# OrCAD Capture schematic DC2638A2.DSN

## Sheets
1 PAGE5: size C; company: ANALOG DEVICES; note: DEMO BOARD BILL OF MATERIALS; note: HIGH EFFICIENCY, POLY-PHASE, DC/DC STEP-DOWN
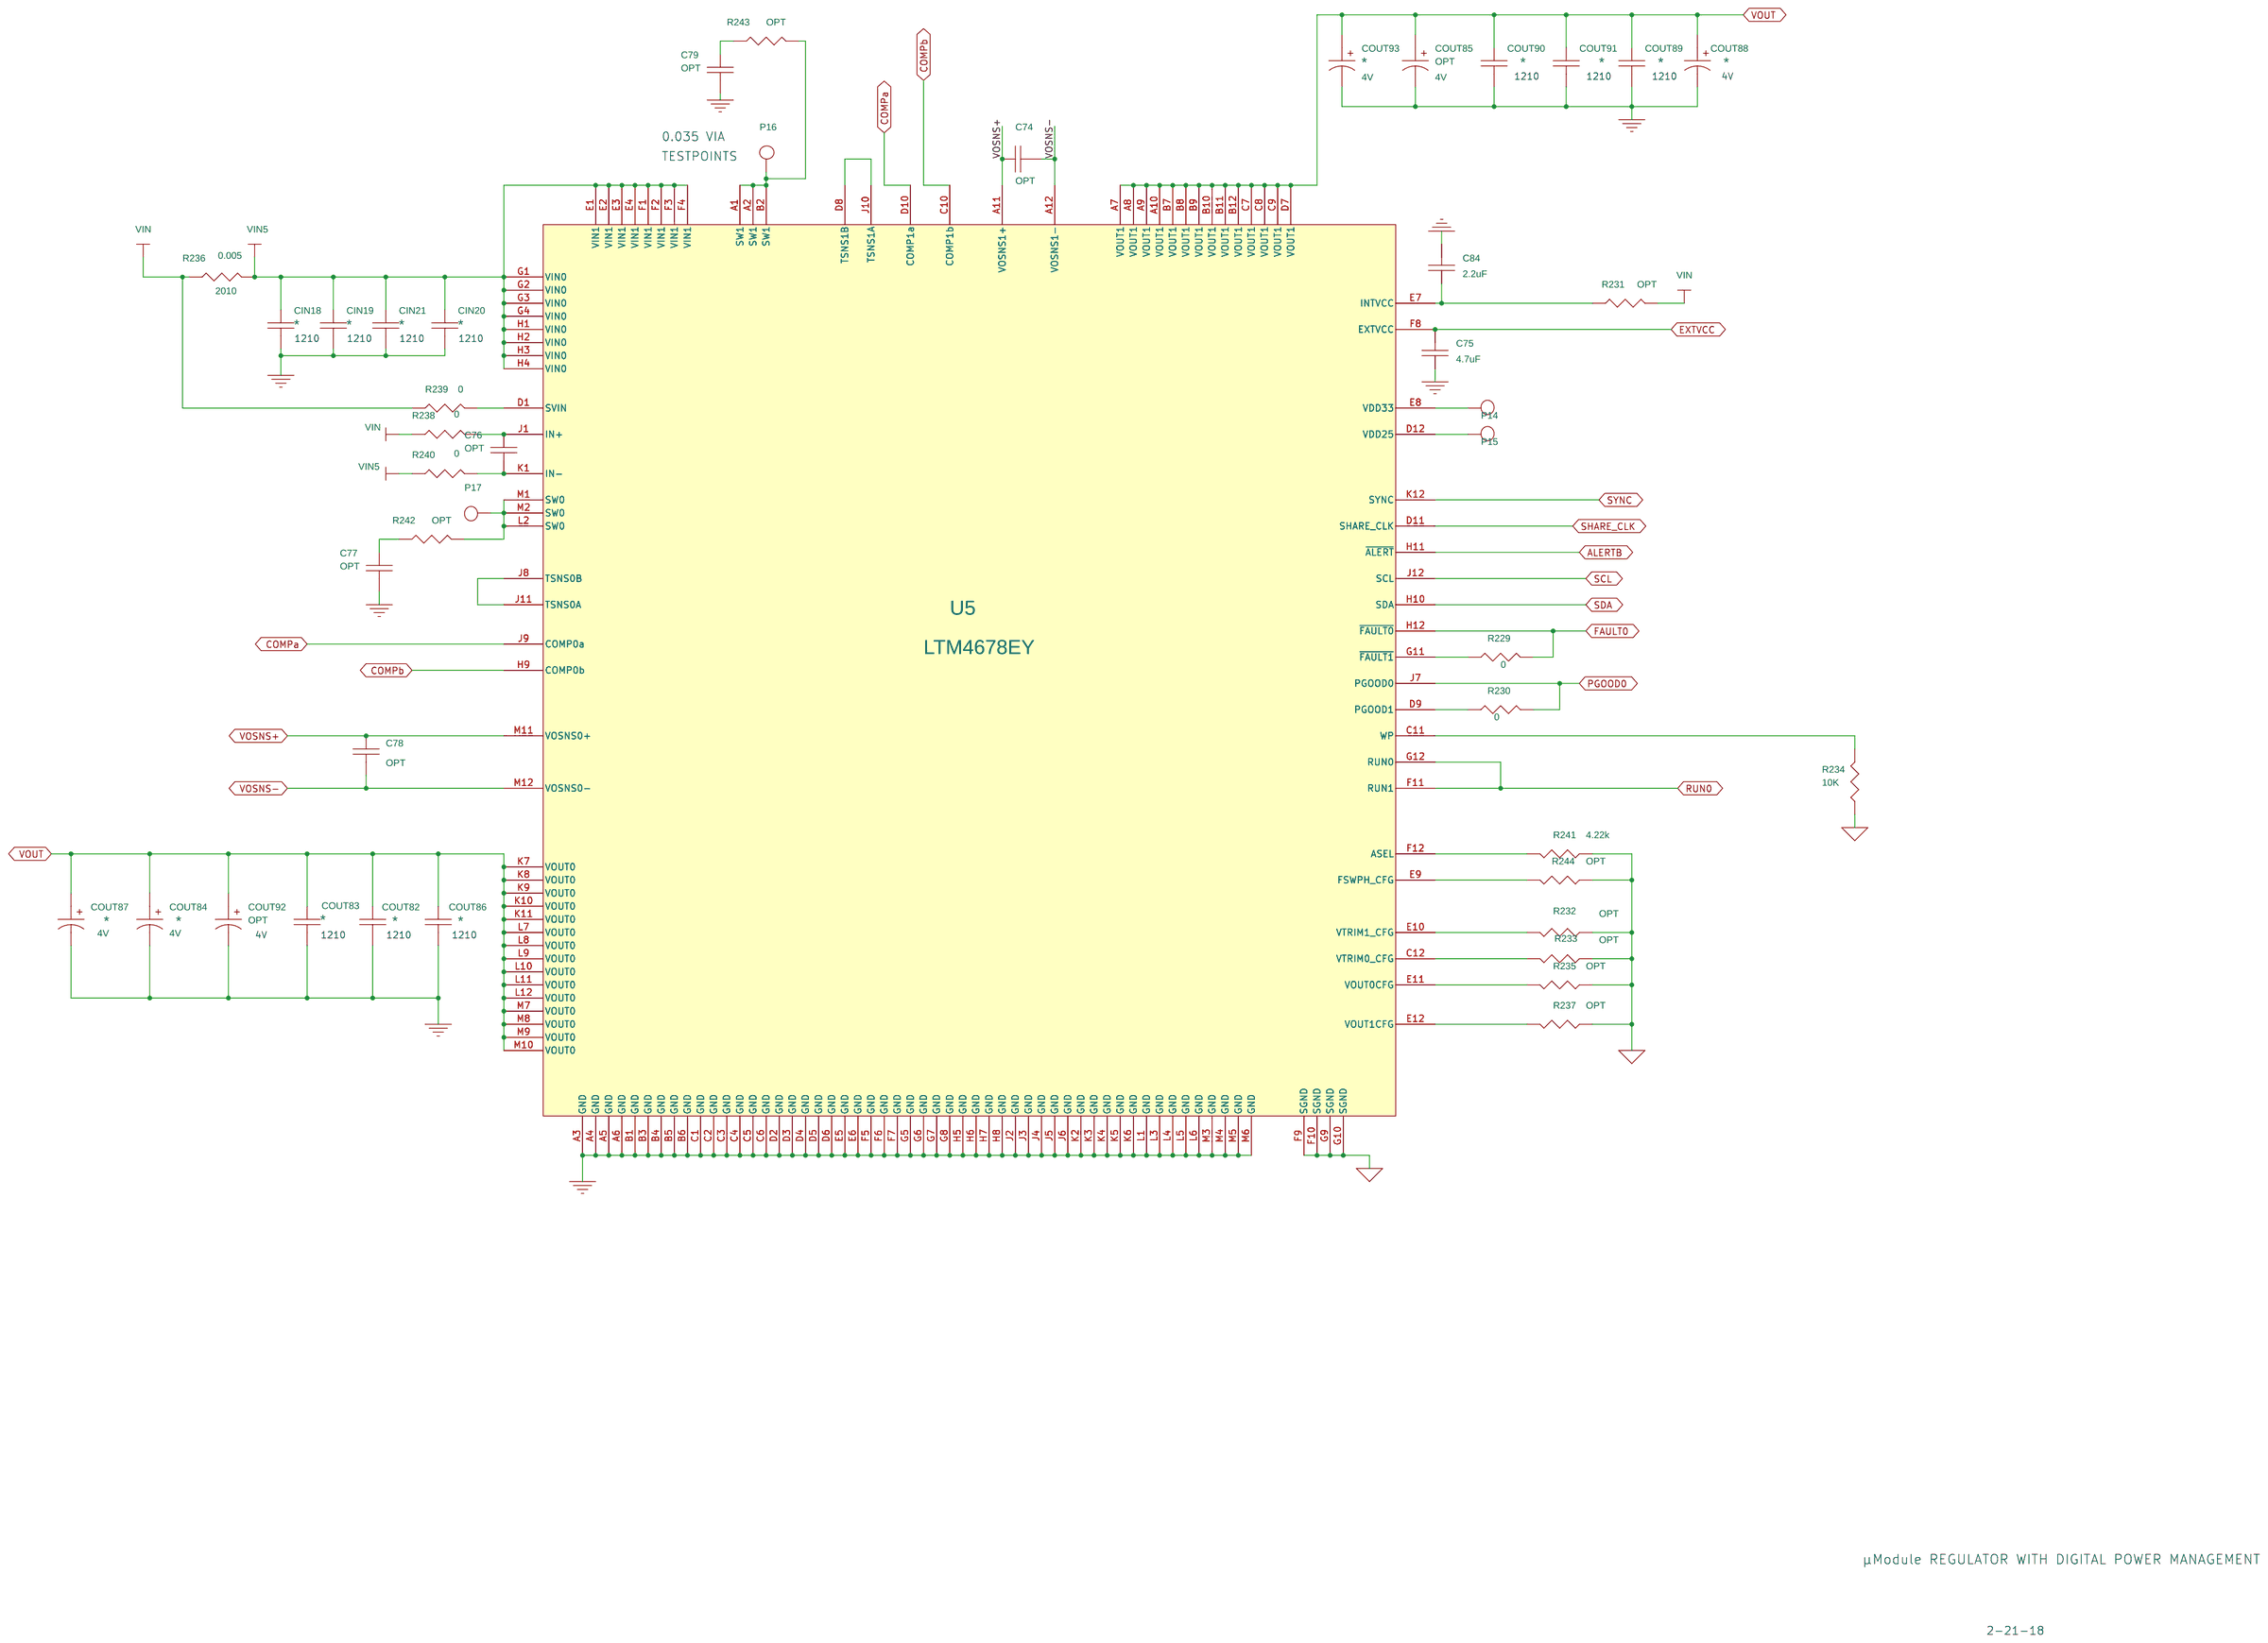
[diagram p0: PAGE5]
2 PAGE4: size C
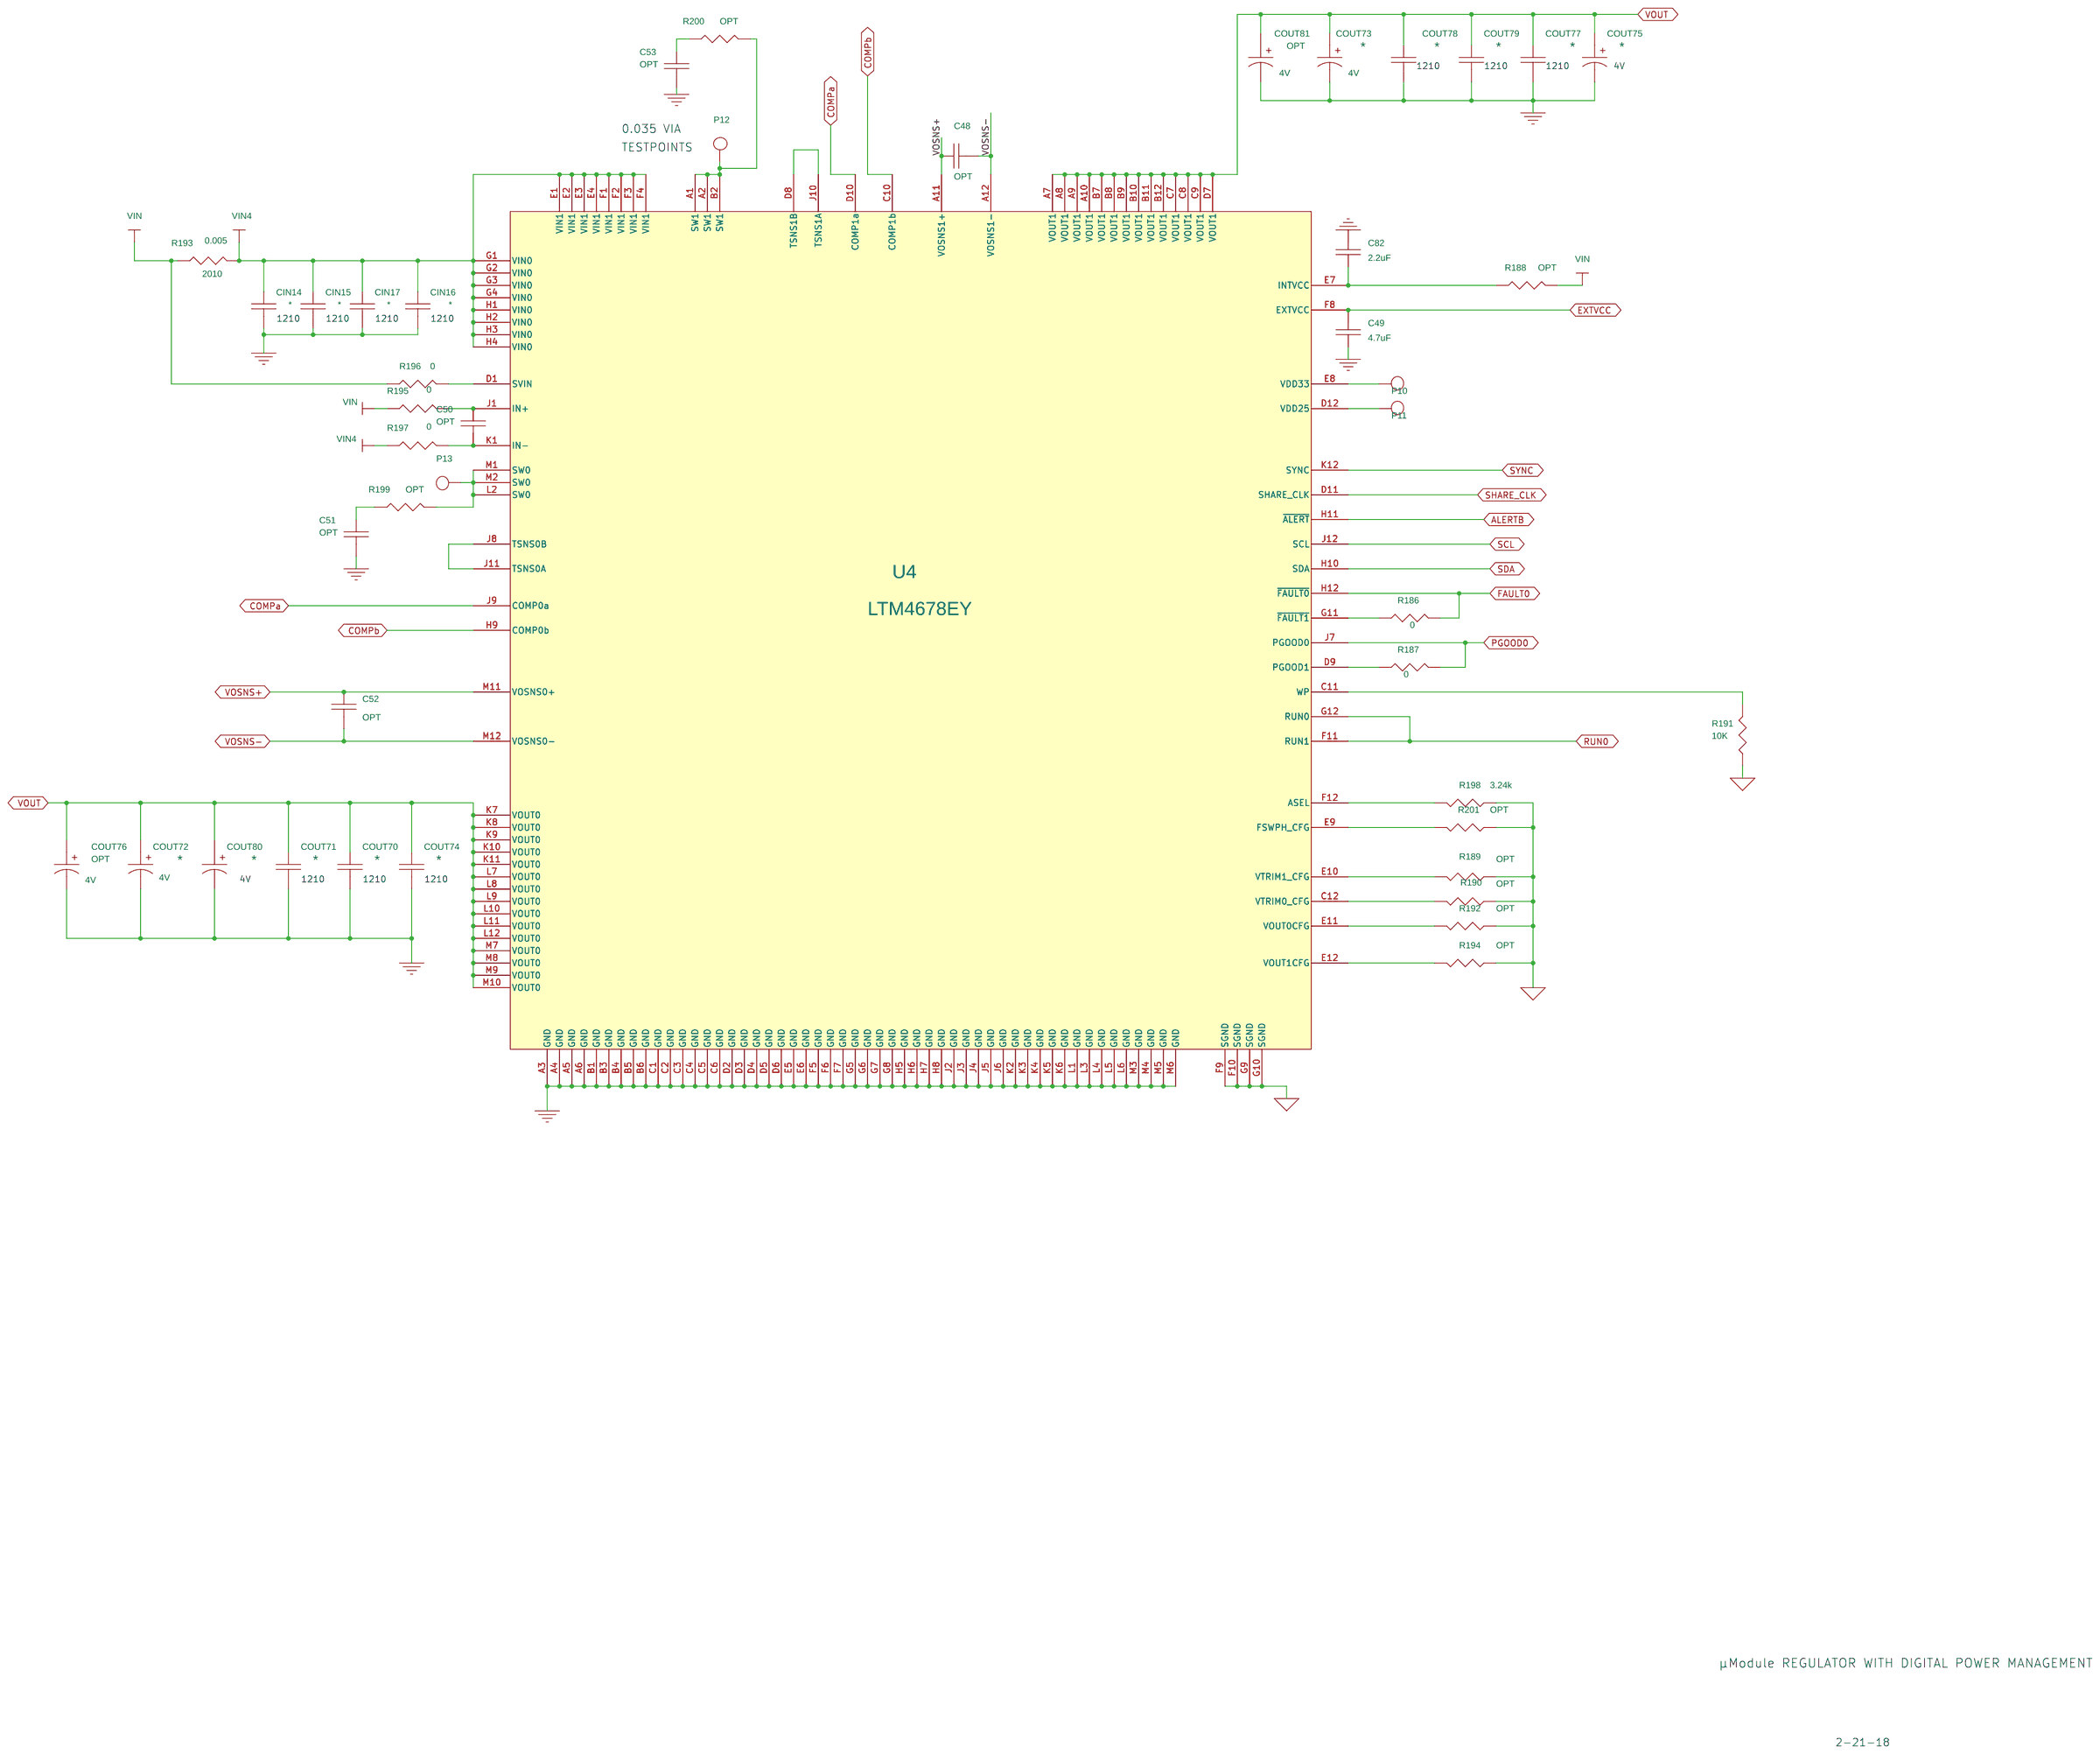
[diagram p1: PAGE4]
3 PAGE3: size C
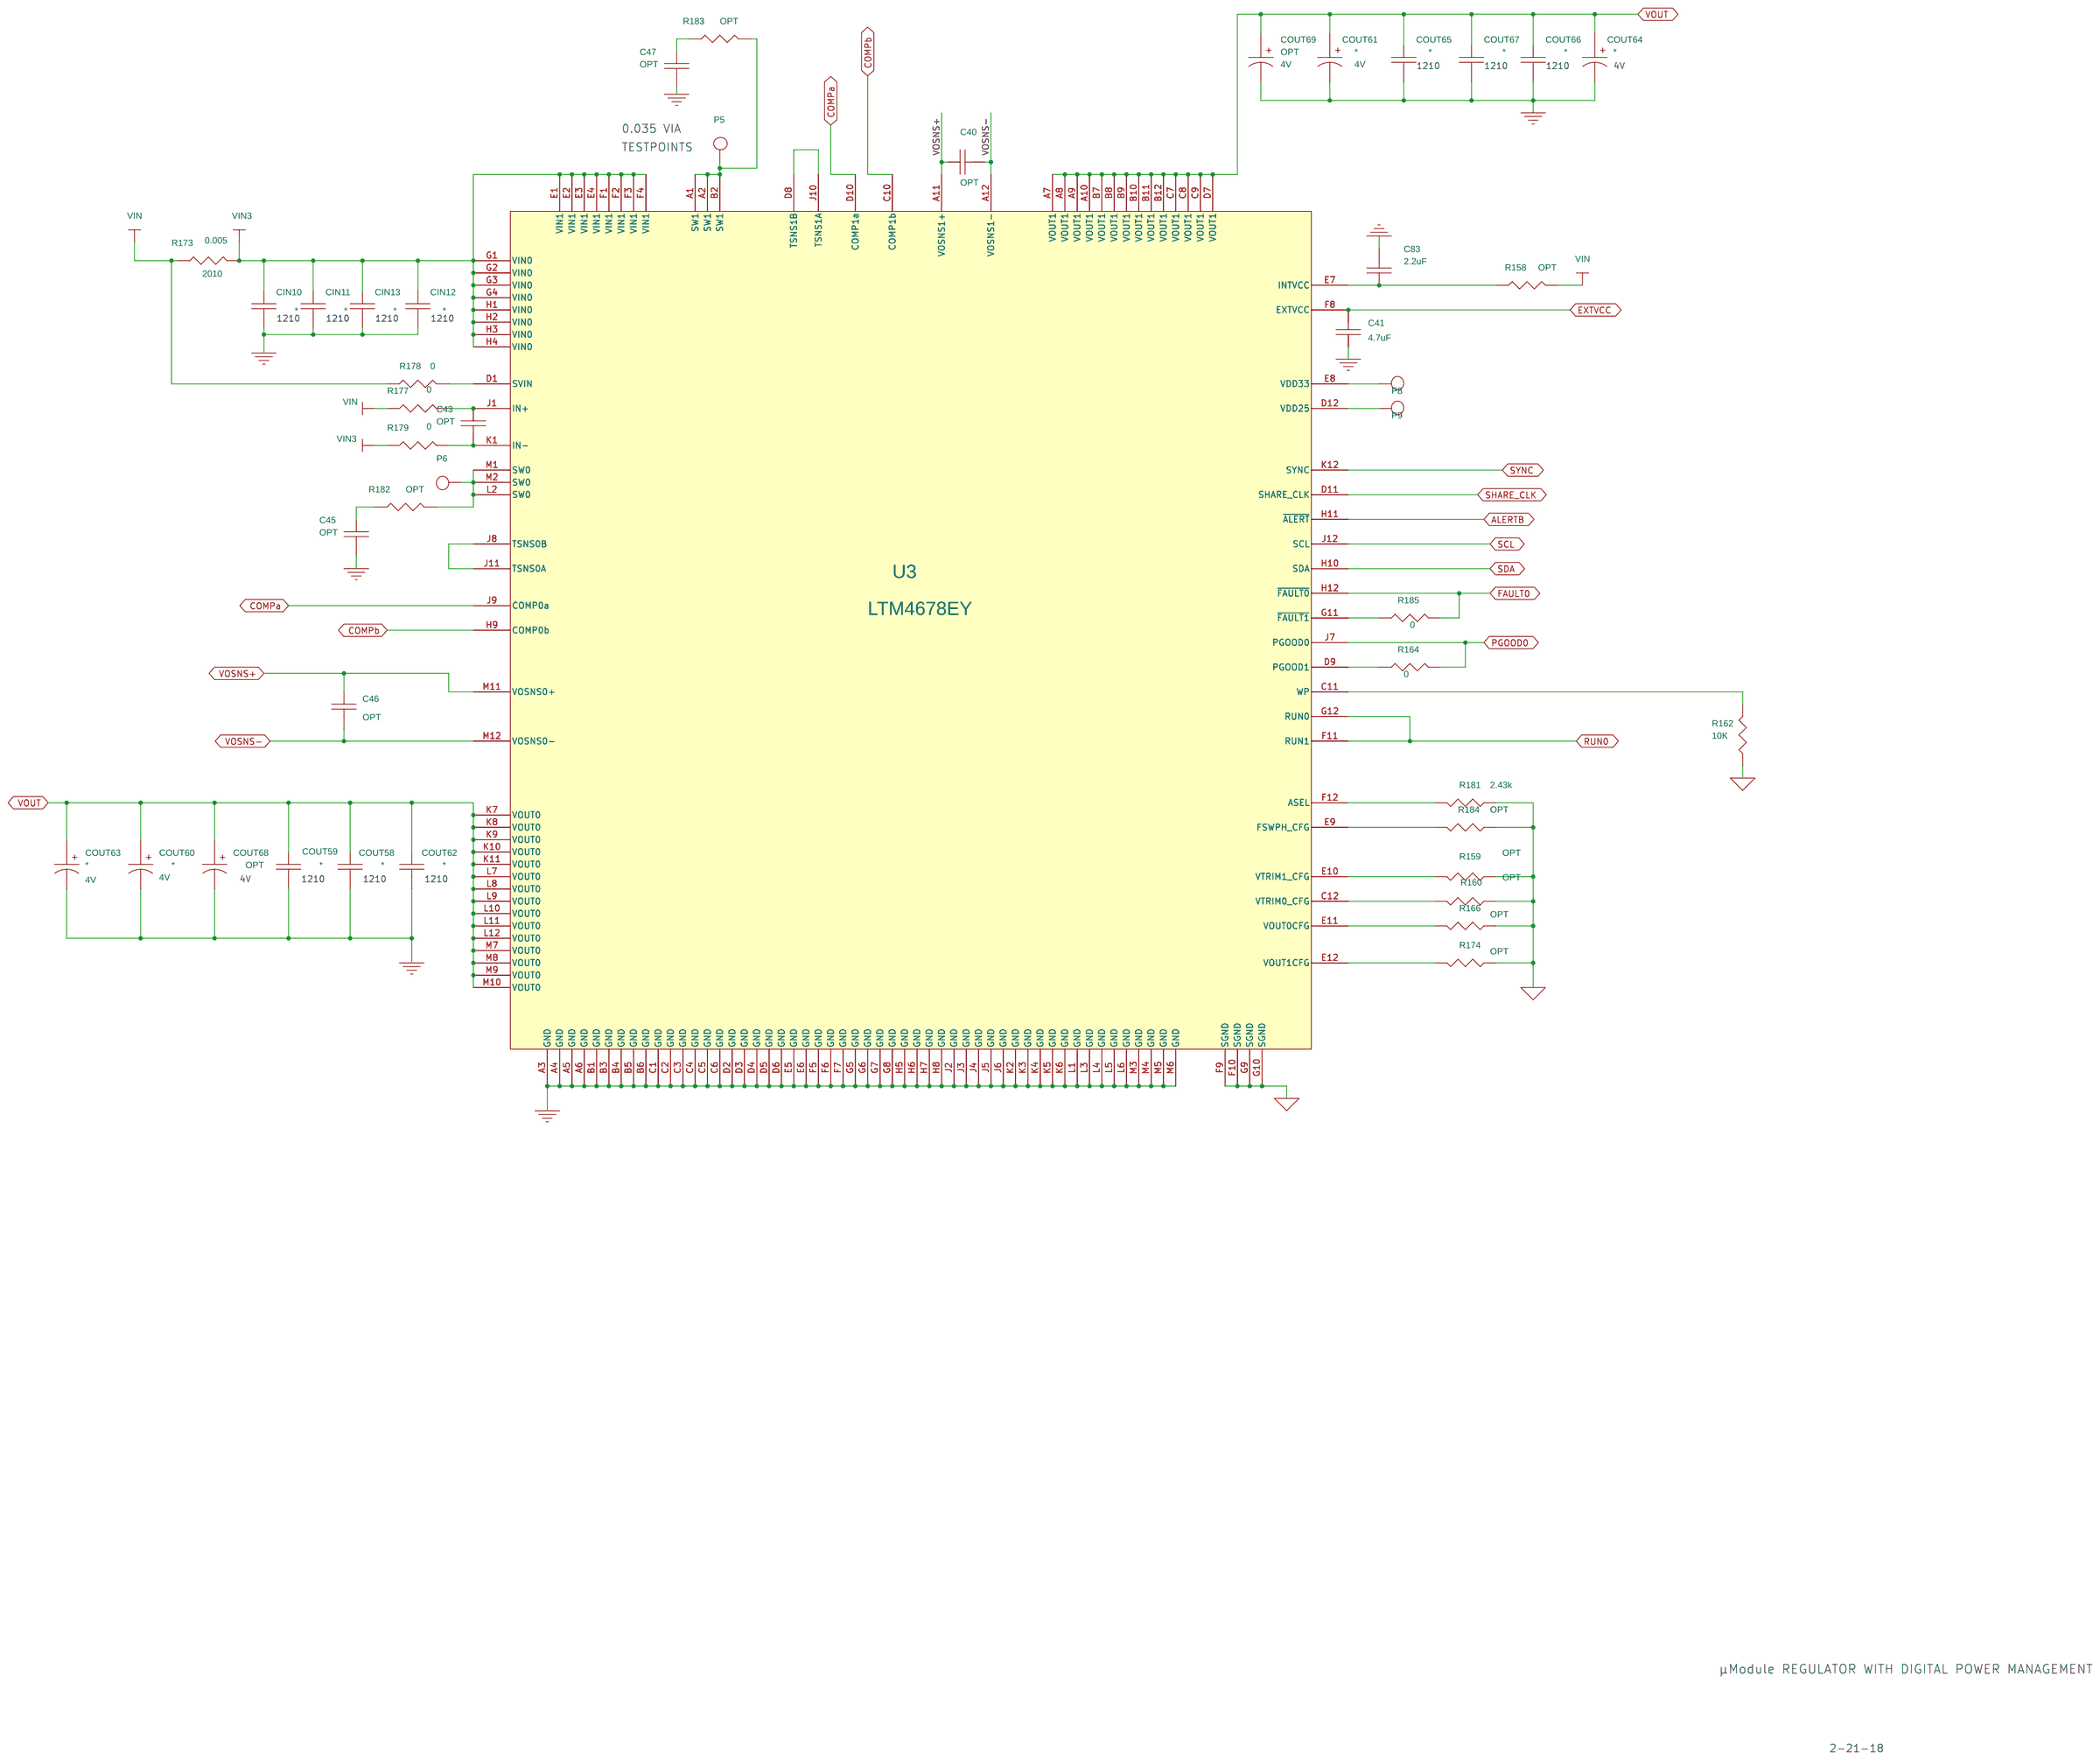
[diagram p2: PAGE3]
4 PAGE2: size C
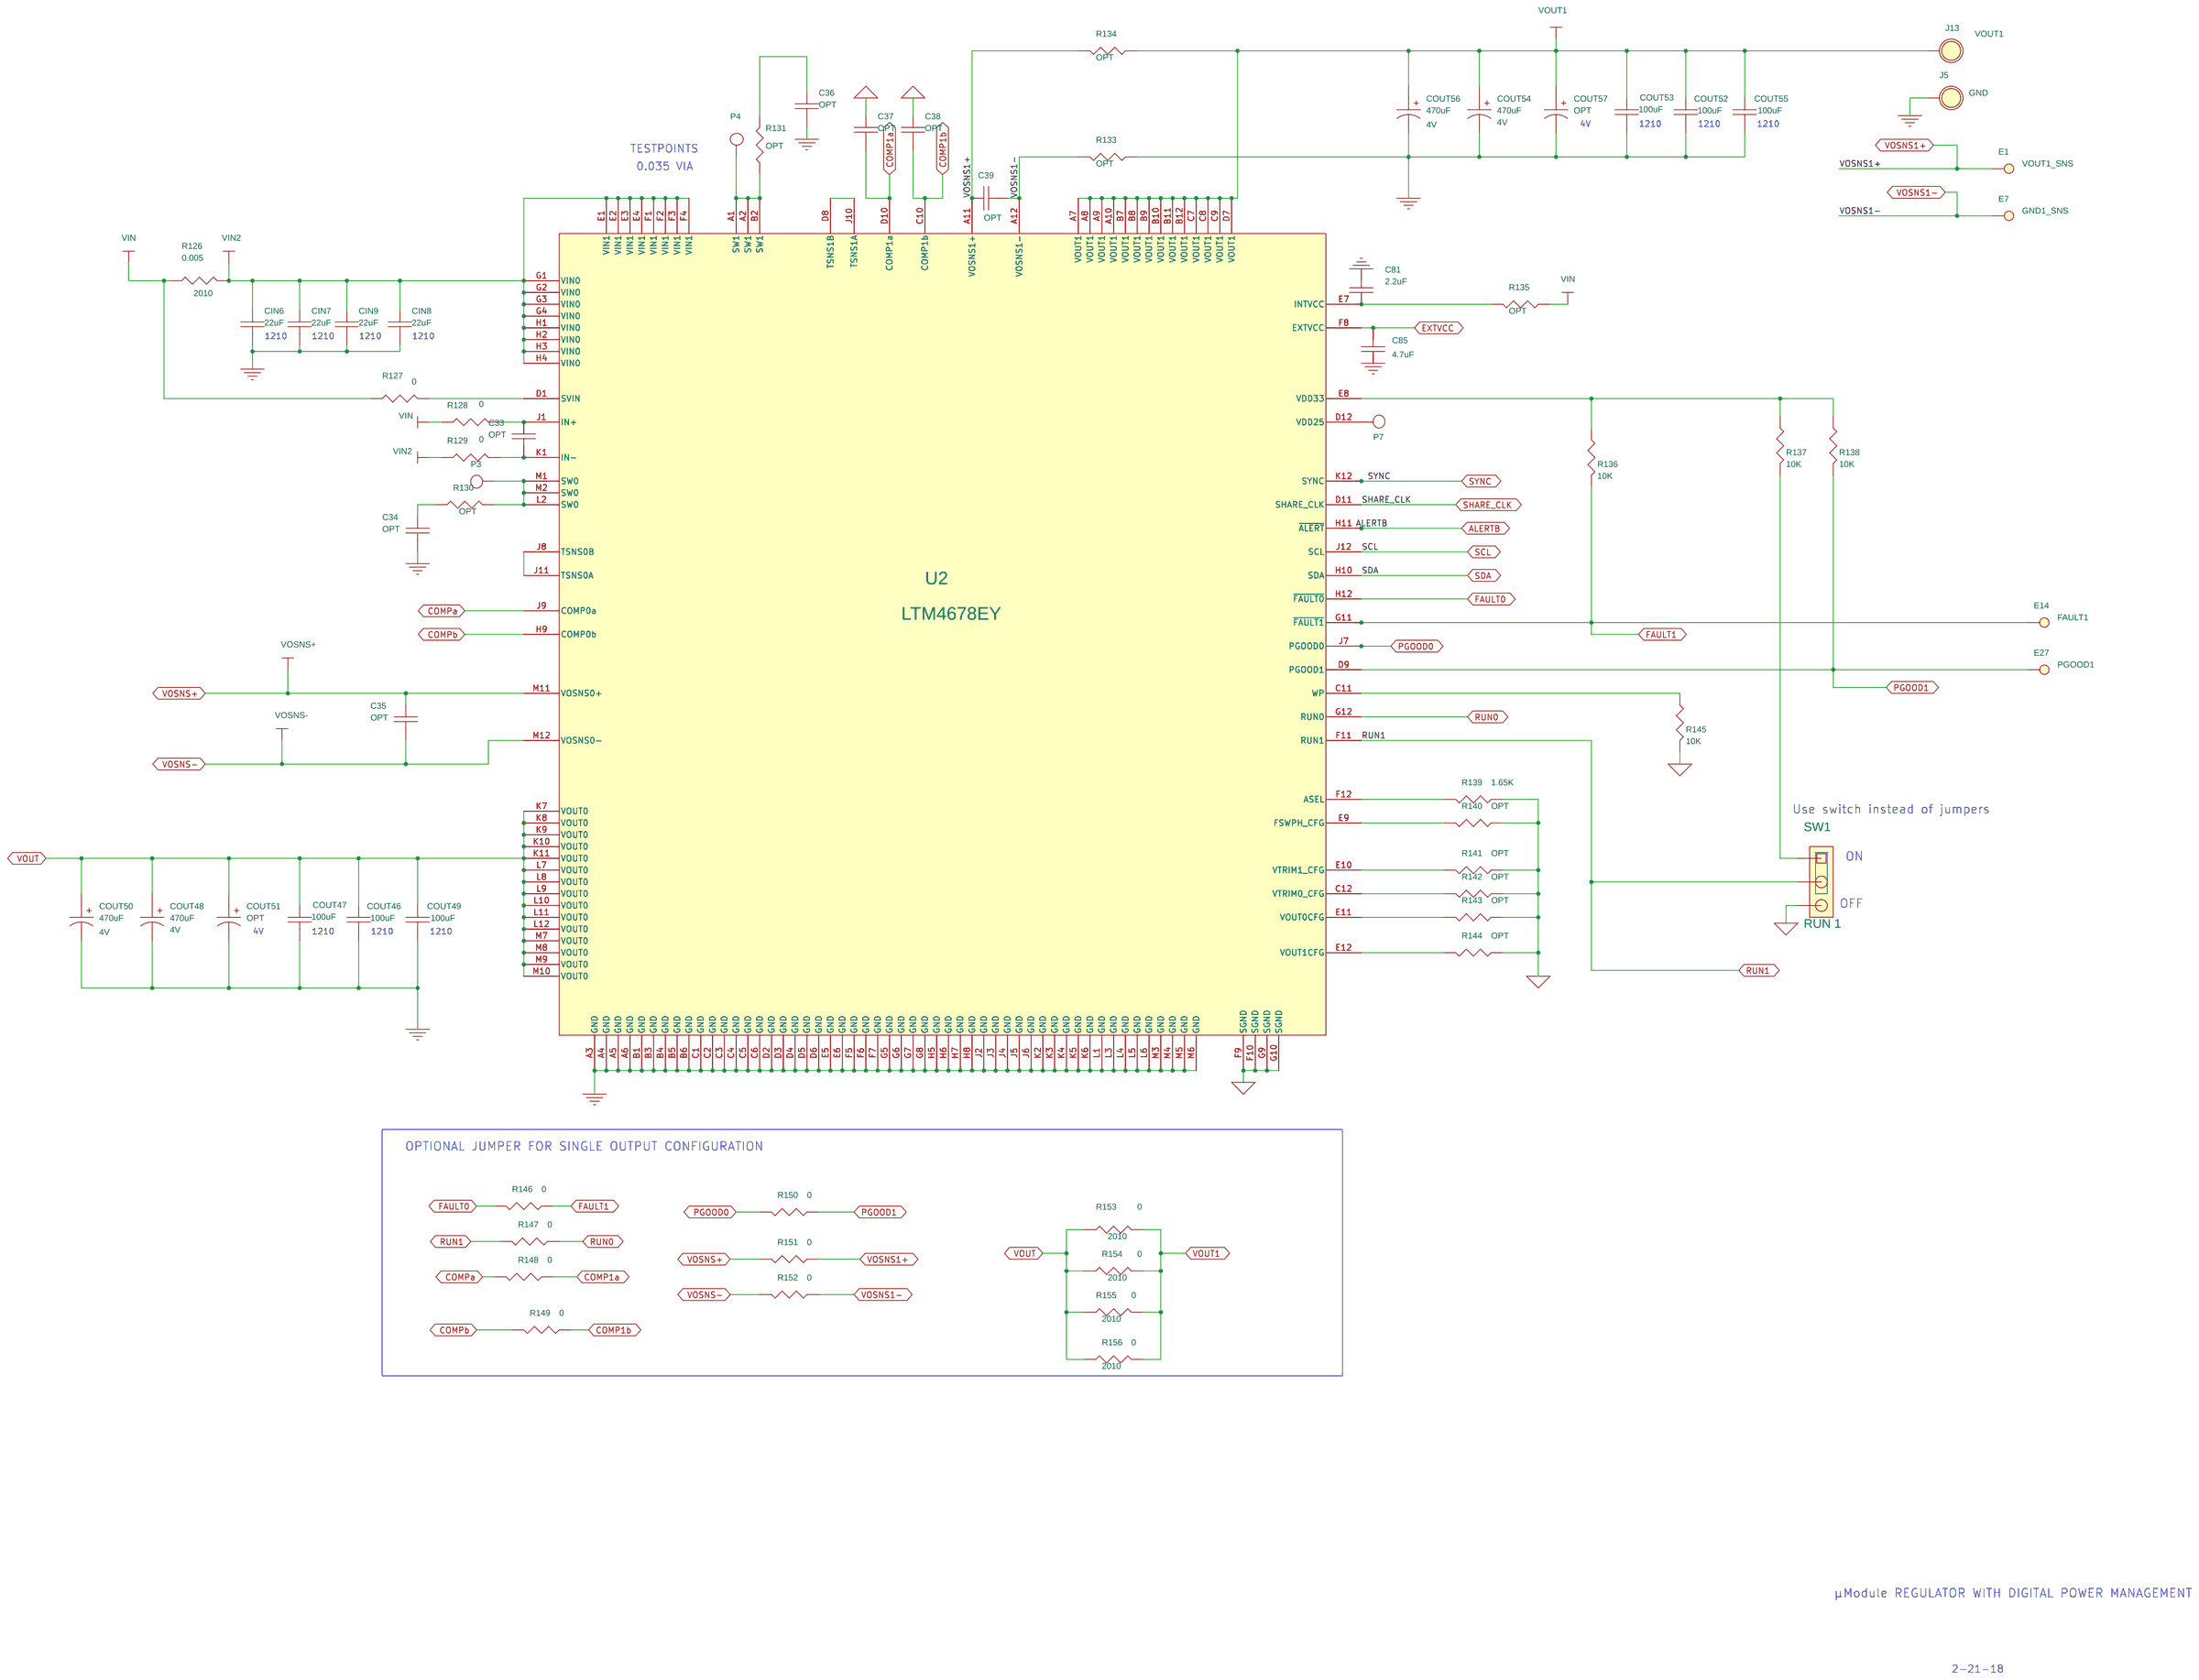
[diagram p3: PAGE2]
5 PAGE7: size C
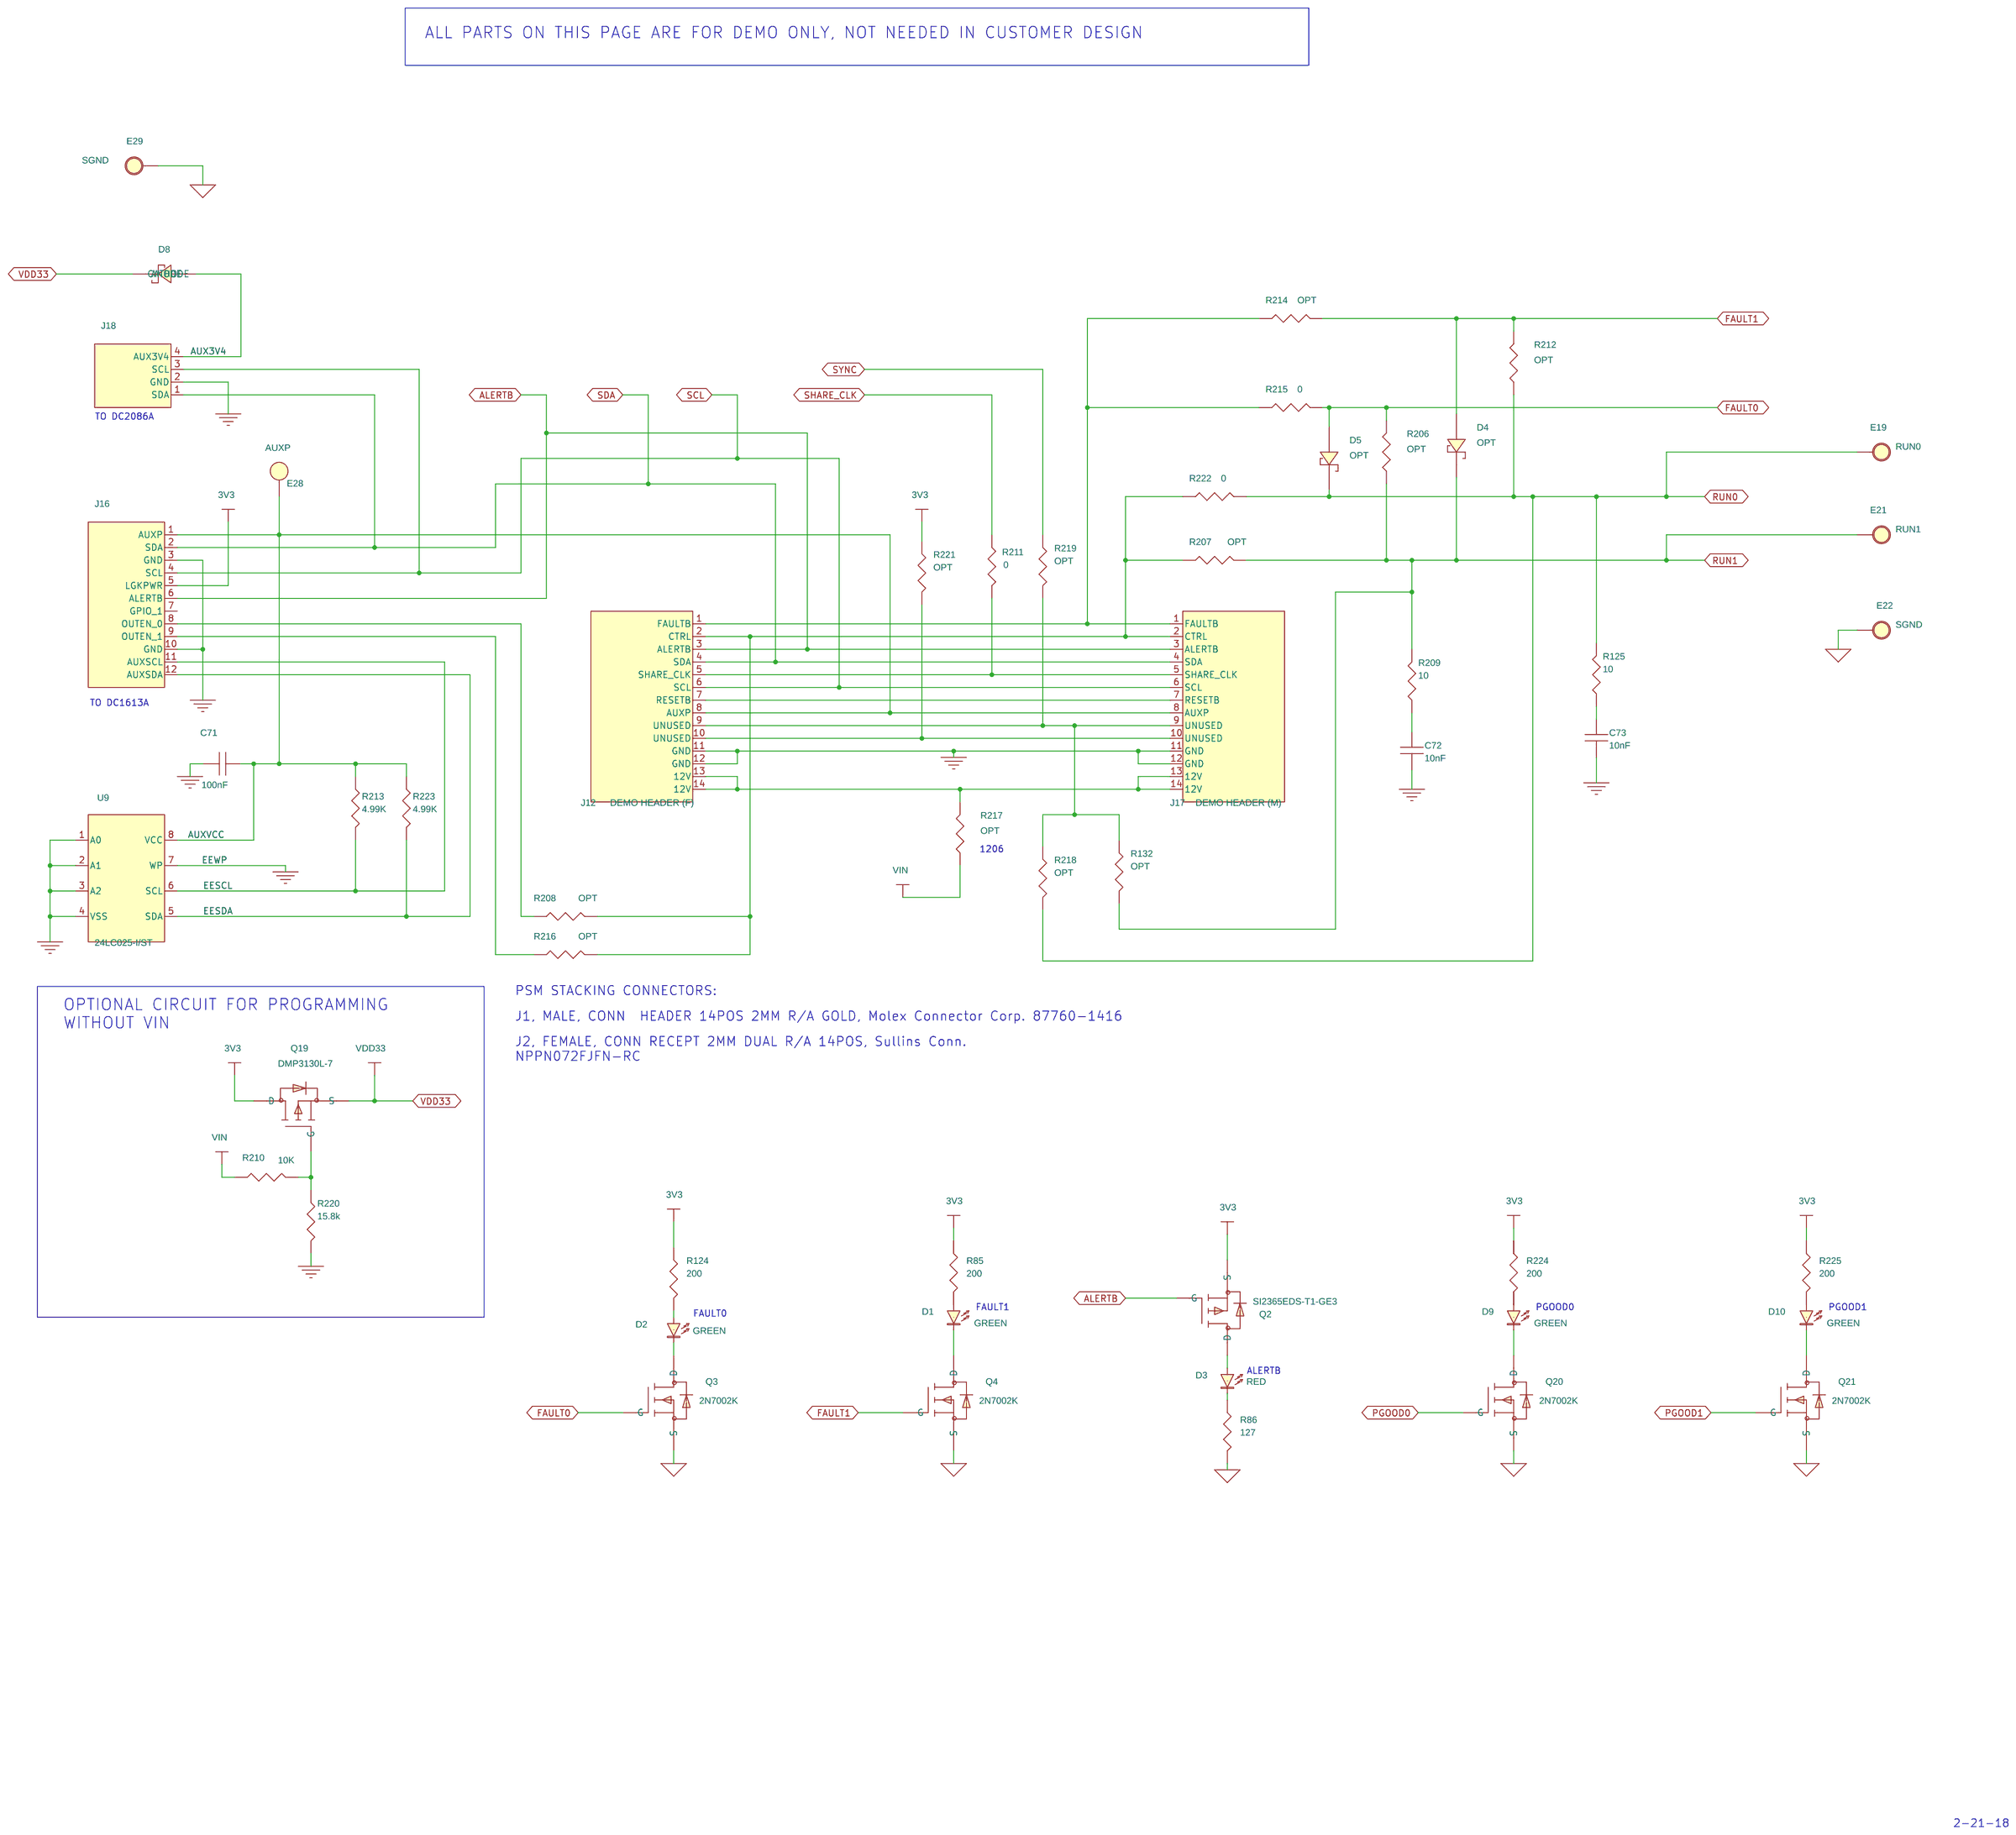
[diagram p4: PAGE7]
6 PAGE1: size C
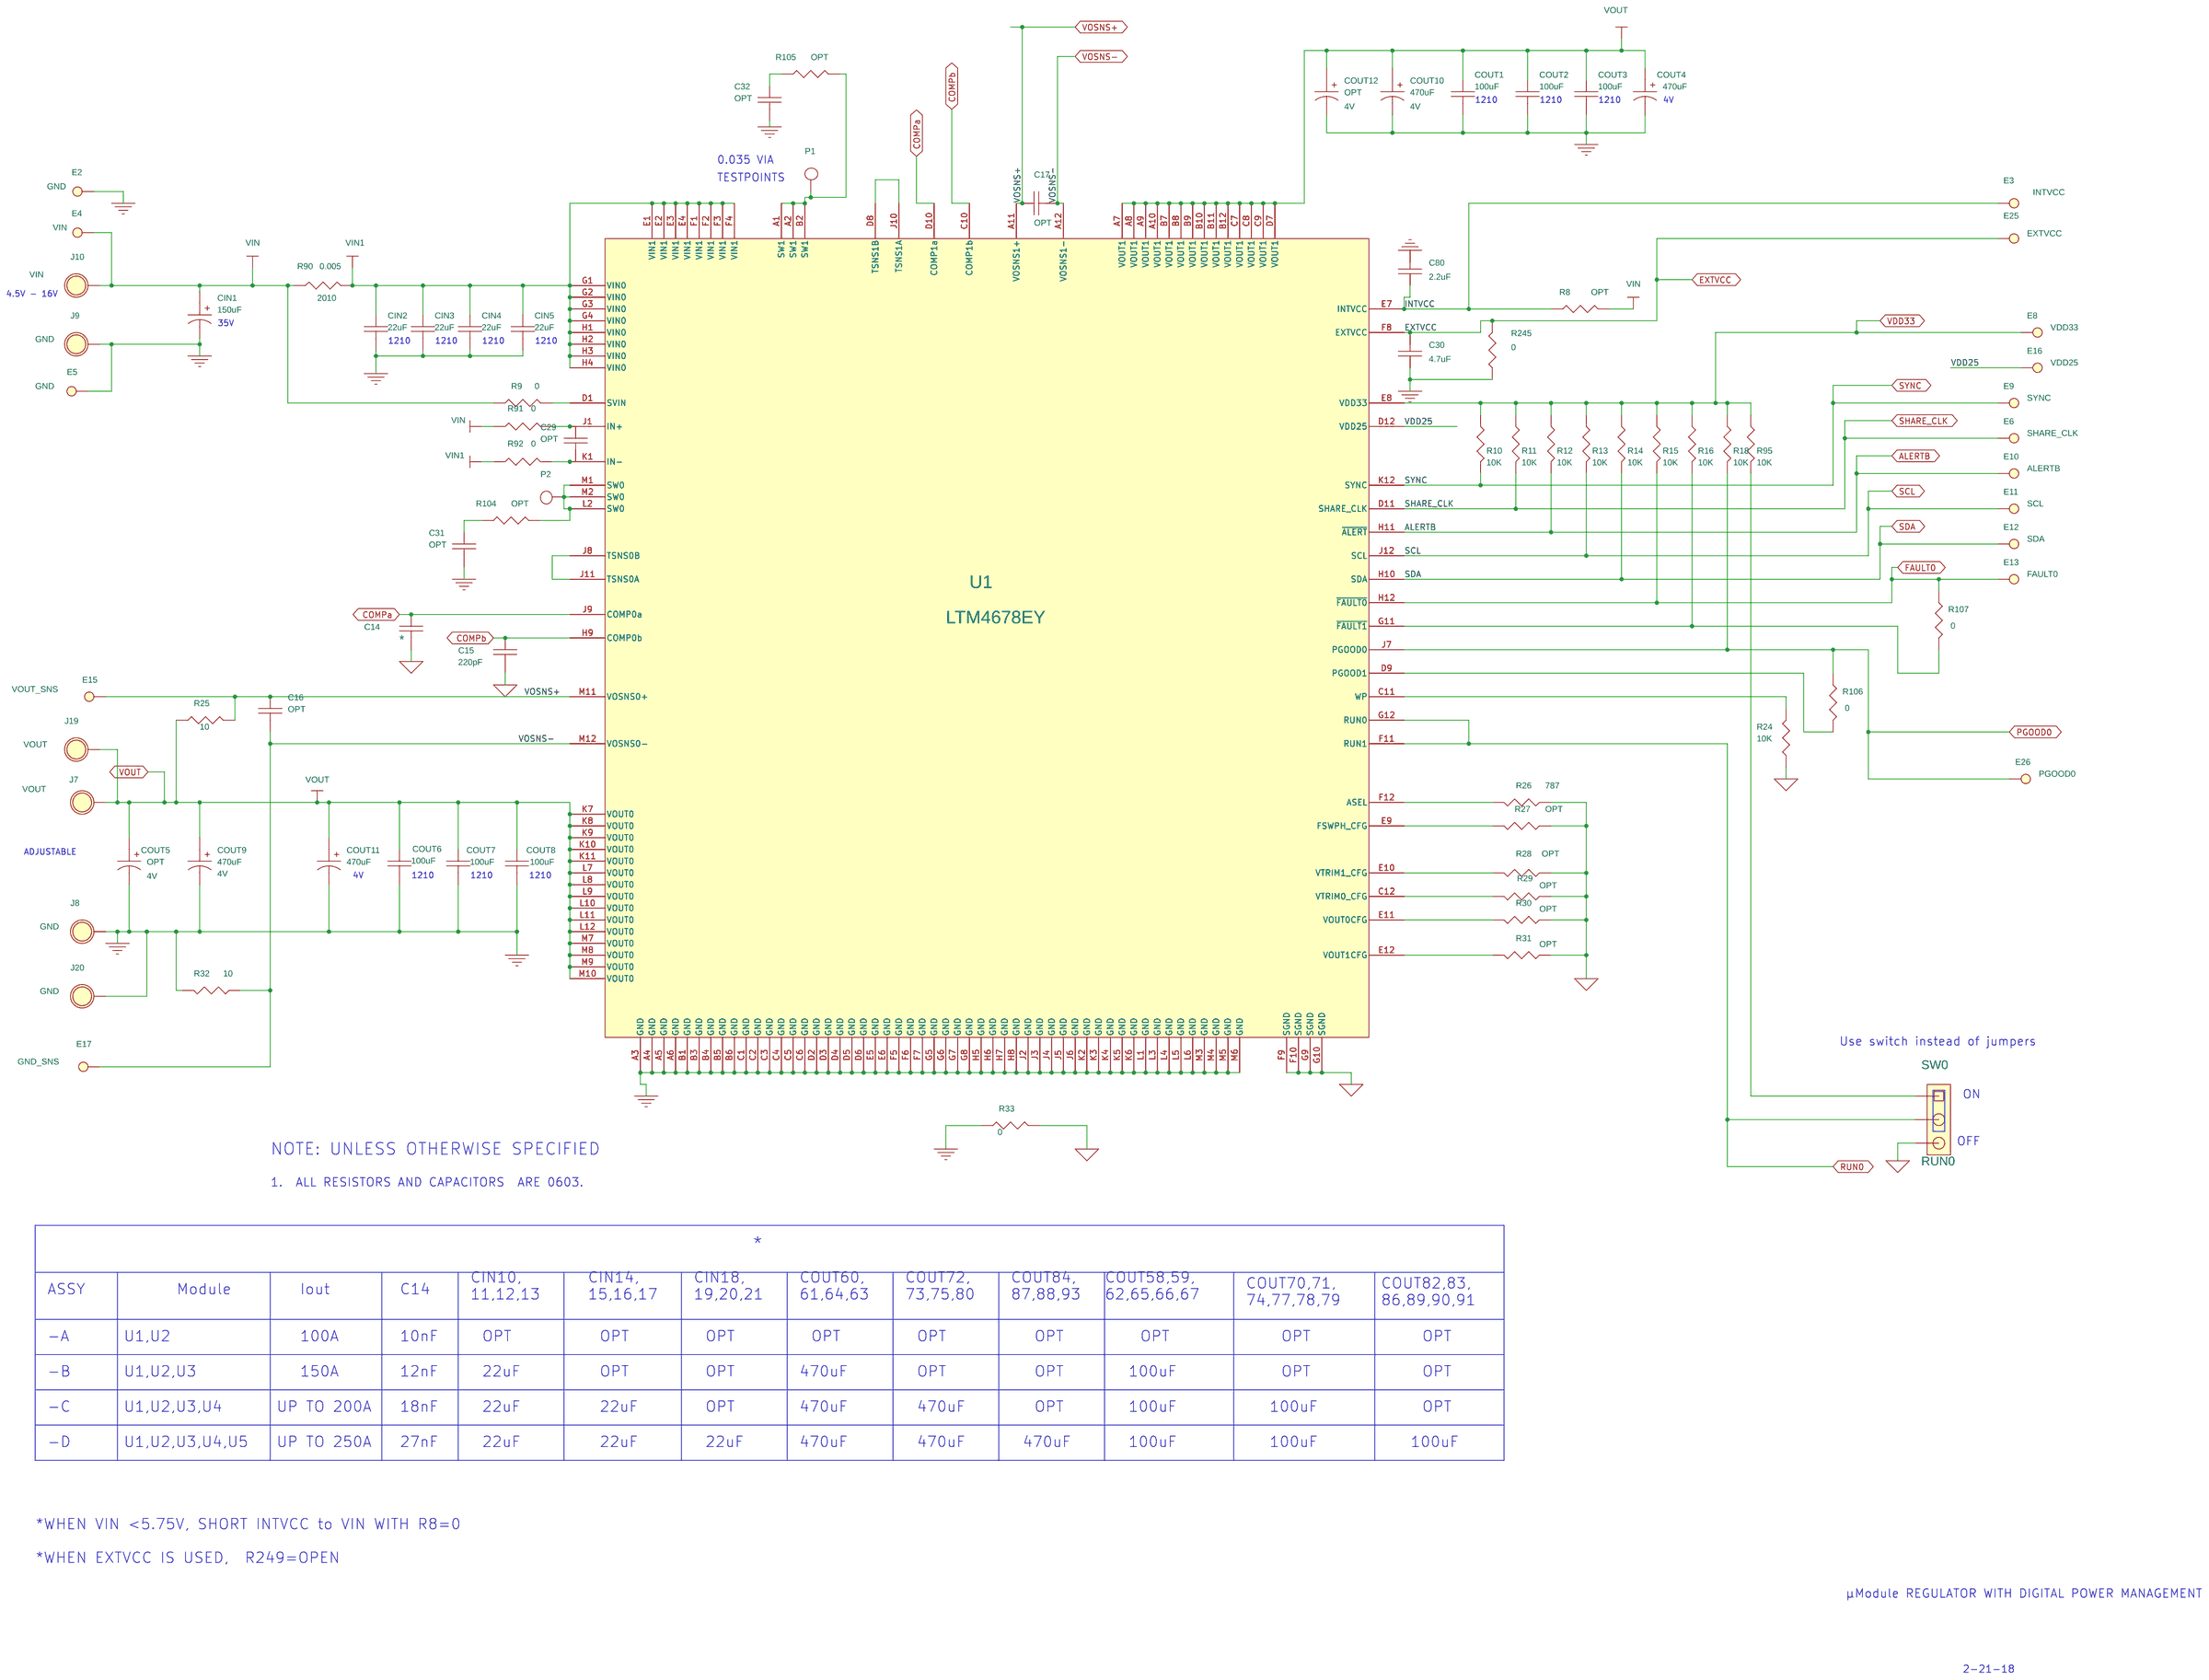
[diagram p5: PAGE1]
7 PAGE6: size B
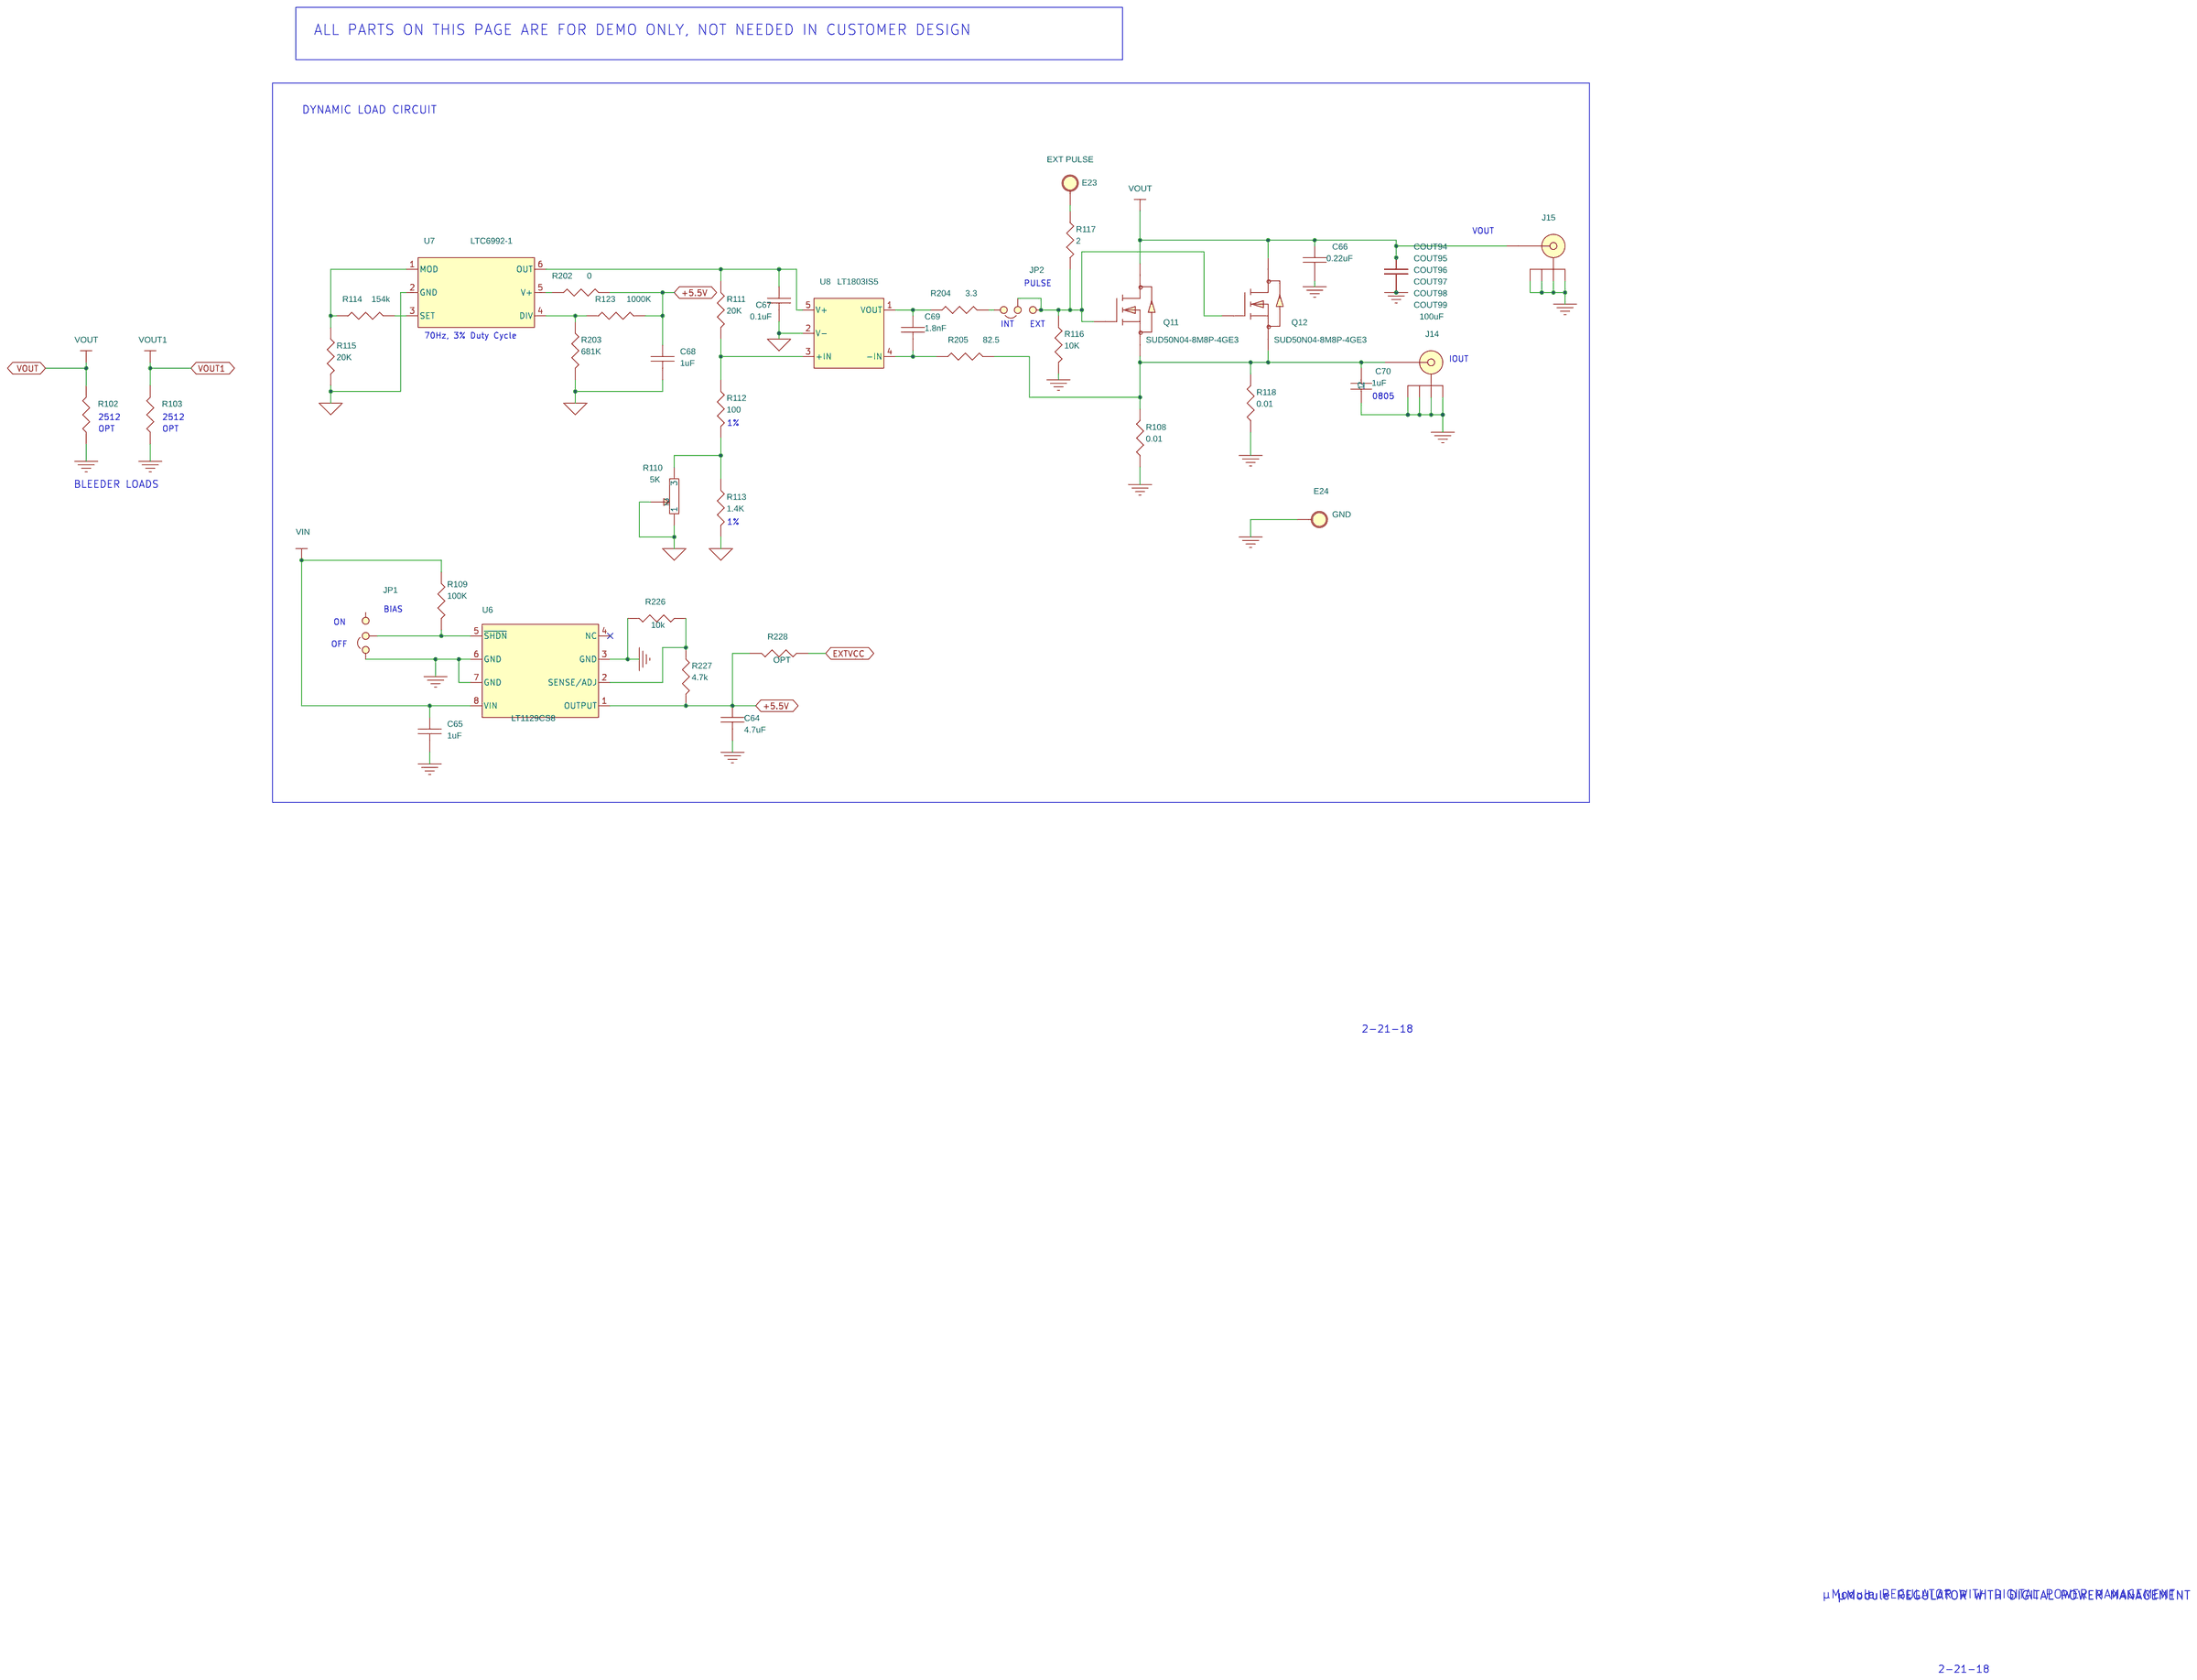
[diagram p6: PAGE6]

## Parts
sheet PAGE1
C14  *  [0603]
C15  220pF  [0603]
C16  OPT  [0603]
C17  OPT  [0603]
C29  OPT  [0603]
C30  4.7uF  [0603]
C31  OPT  [0603]
C32  OPT  [0603]
C80  2.2uF  [0603]
CIN1  150uF  [SANYO\8X10]
CIN2  22uF  [1210]
CIN3  22uF  [1210]
CIN4  22uF  [1210]
CIN5  22uF  [1210]
COUT1  100uF  [1210]
COUT2  100uF  [1210]
COUT3  100uF  [1210]
COUT4  470uF  [D3L]
COUT5  OPT  [D3L]
COUT6  100uF  [1210]
COUT7  100uF  [1210]
COUT8  100uF  [1210]
COUT9  470uF  [D3L]
COUT10  470uF  [D3L]
COUT11  470uF  [D3L]
COUT12  OPT  [D3L]
E2  GND  [TURRETS]
E3  INTVCC  [TURRETS]
E4  TURRETS  [TURRETS]
E5  GND  [TURRETS]
E6  TURRETS  [TURRETS]
E8  VDD33  [TURRETS]
E9  TURRETS  [TURRETS]
E10  TURRETS  [TURRETS]
E11  TURRETS  [TURRETS]
E12  TURRETS  [TURRETS]
E13  TURRETS  [TURRETS]
E15  TURRETS  [TURRETS]
E16  VDD25  [TURRETS]
E17  TURRETS  [TURRETS]
E25  EXTVCC  [TURRETS]
E26  TURRETS  [TURRETS]
J7  BANANA SMALL  [CON\LUG\10]
J8  BANANA SMALL  [CON\LUG\10]
J9  BANANA SMALL  [CON\LUG\10]
J10  BANANA SMALL  [CON\LUG\10]
J19  BANANA SMALL  [CON\LUG\10]
J20  BANANA SMALL  [CON\LUG\10]
P1  TURRETS  [PAD]
P2  TURRETS  [PAD]
R8  OPT  [0603]
R9  0  [0603]
R10  10K  [0603]
R11  10K  [0603]
R12  10K  [0603]
R13  10K  [0603]
R14  10K  [0603]
R15  10K  [0603]
R16  10K  [0603]
R18  10K  [0603]
R24  10K  [0603]
R25  10  [0603]
R26  787  [0603]
R27  OPT  [0603]
R28  OPT  [0603]
R29  OPT  [0603]
R30  OPT  [0603]
R31  OPT  [0603]
R32  10  [0603]
R33  0  [0603]
R90  0.005  [2010]
R91  0  [0603]
R92  0  [0603]
R95  10K  [0603]
R104  OPT  [0603]
R105  OPT  [0603]
R106  0  [0603]
R107  0  [0603]
R245  0  [0603]
SW0  3 Pins 2mm Ctrs.  [HD1X3-079]
U1  LTM4678EY  [a]
sheet PAGE2
C33  OPT  [0603]
C34  OPT  [0603]
C35  OPT  [0603]
C36  OPT  [0603]
C37  OPT  [0603]
C38  OPT  [0603]
C39  OPT  [0603]
C81  2.2uF  [0603]
C85  4.7uF  [0603]
CIN6  22uF  [1210]
CIN7  22uF  [1210]
CIN8  22uF  [1210]
CIN9  22uF  [1210]
COUT46  100uF  [1210]
COUT47  100uF  [1210]
COUT48  470uF  [D3L]
COUT49  100uF  [1210]
COUT50  470uF  [D3L]
COUT51  OPT  [D3L]
COUT52  100uF  [1210]
COUT53  100uF  [1210]
COUT54  470uF  [D3L]
COUT55  100uF  [1210]
COUT56  470uF  [D3L]
COUT57  OPT  [D3L]
E1  TURRETS  [TURRETS]
E7  TURRETS  [TURRETS]
E14  TURRETS  [TURRETS]
E27  TURRETS  [TURRETS]
J5  BANANA SMALL  [CON\LUG\10]
J13  BANANA SMALL  [CON\LUG\10]
P3  TURRETS  [PAD]
P4  TURRETS  [PAD]
P7  TURRETS  [PAD]
R126  0.005  [2010]
R127  0  [0603]
R128  0  [0603]
R129  0  [0603]
R130  OPT  [0603]
R131  OPT  [0603]
R133  OPT  [0603]
R134  OPT  [0603]
R135  OPT  [0603]
R136  10K  [0603]
R137  10K  [0603]
R138  10K  [0603]
R139  1.65K  [0603]
R140  OPT  [0603]
R141  OPT  [0603]
R142  OPT  [0603]
R143  OPT  [0603]
R144  OPT  [0603]
R145  10K  [0603]
R146  0  [0603]
R147  0  [0603]
R148  0  [0603]
R149  0  [0603]
R150  0  [0603]
R151  0  [0603]
R152  0  [0603]
R153  0  [2010]
R154  0  [2010]
R155  0  [2010]
R156  0  [2010]
SW1  3 Pins 2mm Ctrs.  [HD1X3-079]
U2  LTM4678EY  [a]
sheet PAGE3
C40  OPT  [0603]
C41  4.7uF  [0603]
C43  OPT  [0603]
C45  OPT  [0603]
C46  OPT  [0603]
C47  OPT  [0603]
C83  2.2uF  [0603]
CIN10  *  [1210]
CIN11  *  [1210]
CIN12  *  [1210]
CIN13  *  [1210]
COUT58  *  [1210]
COUT59  *  [1210]
COUT60  *  [D3L]
COUT61  *  [D3L]
COUT62  *  [1210]
COUT63  *  [D3L]
COUT64  *  [D3L]
COUT65  *  [1210]
COUT66  *  [1210]
COUT67  *  [1210]
COUT68  OPT  [D3L]
COUT69  OPT  [D3L]
P5  TURRETS  [PAD]
P6  TURRETS  [PAD]
P8  TURRETS  [PAD]
P9  TURRETS  [PAD]
R158  OPT  [0603]
R159  OPT  [0603]
R160  OPT  [0603]
R162  10K  [0603]
R164  0  [0603]
R166  OPT  [0603]
R173  0.005  [2010]
R174  OPT  [0603]
R177  0  [0603]
R178  0  [0603]
R179  0  [0603]
R181  2.43k  [0603]
R182  OPT  [0603]
R183  OPT  [0603]
R184  OPT  [0603]
R185  0  [0603]
U3  LTM4678EY  [a]
sheet PAGE4
C48  OPT  [0603]
C49  4.7uF  [0603]
C50  OPT  [0603]
C51  OPT  [0603]
C52  OPT  [0603]
C53  OPT  [0603]
C82  2.2uF  [0603]
CIN14  *  [1210]
CIN15  *  [1210]
CIN16  *  [1210]
CIN17  *  [1210]
COUT70  *  [1210]
COUT71  *  [1210]
COUT72  *  [D3L]
COUT73  *  [D3L]
COUT74  *  [1210]
COUT75  *  [D3L]
COUT76  OPT  [D3L]
COUT77  *  [1210]
COUT78  *  [1210]
COUT79  *  [1210]
COUT80  *  [D3L]
COUT81  OPT  [D3L]
P10  TURRETS  [PAD]
P11  TURRETS  [PAD]
P12  TURRETS  [PAD]
P13  TURRETS  [PAD]
R186  0  [0603]
R187  0  [0603]
R188  OPT  [0603]
R189  OPT  [0603]
R190  OPT  [0603]
R191  10K  [0603]
R192  OPT  [0603]
R193  0.005  [2010]
R194  OPT  [0603]
R195  0  [0603]
R196  0  [0603]
R197  0  [0603]
R198  3.24k  [0603]
R199  OPT  [0603]
R200  OPT  [0603]
R201  OPT  [0603]
U4  LTM4678EY  [a]
sheet PAGE5
C74  OPT  [0603]
C75  4.7uF  [0603]
C76  OPT  [0603]
C77  OPT  [0603]
C78  OPT  [0603]
C79  OPT  [0603]
C84  2.2uF  [0603]
CIN18  *  [1210]
CIN19  *  [1210]
CIN20  *  [1210]
CIN21  *  [1210]
COUT82  *  [1210]
COUT83  *  [1210]
COUT84  *  [D3L]
COUT85  OPT  [D3L]
COUT86  *  [1210]
COUT87  *  [D3L]
COUT88  *  [D3L]
COUT89  *  [1210]
COUT90  *  [1210]
COUT91  *  [1210]
COUT92  OPT  [D3L]
COUT93  *  [D3L]
P14  TURRETS  [PAD]
P15  TURRETS  [PAD]
P16  TURRETS  [PAD]
P17  TURRETS  [PAD]
R229  0  [0603]
R230  0  [0603]
R231  OPT  [0603]
R232  OPT  [0603]
R233  OPT  [0603]
R234  10K  [0603]
R235  OPT  [0603]
R236  0.005  [2010]
R237  OPT  [0603]
R238  0  [0603]
R239  0  [0603]
R240  0  [0603]
R241  4.22k  [0603]
R242  OPT  [0603]
R243  OPT  [0603]
R244  OPT  [0603]
U5  LTM4678EY  [a]
sheet PAGE6
C64  4.7uF  [0603]
C65  1uF  [1206]
C66  0.22uF  [0805]
C67  0.1uF  [1206]
C68  1uF  [1206]
C69  1.8nF  [0603]
C70  1uF  [0805]
COUT94  100uF  [1210]
COUT95  100uF  [1210]
COUT96  100uF  [1210]
COUT97  100uF  [1210]
COUT98  100uF  [1210]
COUT99  100uF  [1210]
E23  TURRETS  [TURRETS]
E24  TURRETS  [TURRETS]
J14  XXX  [BNC]
J15  XXX  [BNC]
JP1  JP3X1/079\NO\12  [HD1X3-079]
JP2  JP3X1/079\NO\12  [HD1X3-079]
Q11  SUD50N04-8M8P-4GE3  [TO-252]
Q12  SUD50N04-8M8P-4GE3  [TO-252]
R102  OPT  [2512SENSE]
R103  OPT  [2512SENSE]
R108  0.01  [2010]
R109  100K  [0603]
R110  5K  [POTENTIOMETER/3386]
R111  20K  [0603]
R112  100  [0603]
R113  1.4K  [0603]
R114  154k  [0603]
R115  20K  [0603]
R116  10K  [0603]
R117  2  [0603]
R118  0.01  [2010]
R123  1000K  [0603]
R202  0  [0603]
R203  681K  [0603]
R204  3.3  [0603]
R205  82.5  [0603]
R226  10k  [0603]
R227  4.7k  [0603]
R228  OPT  [0603]
U6  LT1129CS8  [SO8NB]
U7  LTC6992-1  [S6-TSOT23]
U8  LT1803IS5  [S5-TSOT23]
sheet PAGE7
C71  100nF  [0603]
C72  10nF  [0603]
C73  10nF  [0603]
D1  GREEN  [led]
D2  GREEN  [led]
D3  RED  [led]
D4  OPT  [SOD323]
D5  OPT  [SOD323]
D8  DIODE SCHOTTKY  [PMEG2005AEL]
D9  GREEN  [led]
D10  GREEN  [led]
E19  TURRETS  [TURRETS]
E21  TURRETS  [TURRETS]
E22  SGND  [TURRETS]
E28  AUXP  [TURRETS]
E29  SGND  [TURRETS]
J12  DEMO HEADER (F)  [NPPN072FJFN-RC]
J16  HD2X6-079  [HD2X6-079-MOLEX]
J17  DEMO HEADER (M)  [NPPN072FJFN]
J18  HD2X6-079-PMBUS_0  [DF3A-4P-2DSA]
Q2  SI2365EDS-T1-GE3  [SOT-23]
Q3  2N7002K  [SOT-23]
Q4  2N7002K  [SOT-23]
Q19  DMP3130L-7  [SOT-23]
Q20  2N7002K  [SOT-23]
Q21  2N7002K  [SOT-23]
R85  200  [0603]
R86  127  [0603]
R124  200  [0603]
R125  10  [0603]
R132  OPT  [0603]
R206  OPT  [0603]
R207  OPT  [0603]
R208  OPT  [0603]
R209  10  [0603]
R210  10K  [0603]
R211  0  [0603]
R212  OPT  [0603]
R213  4.99K  [0603]
R214  OPT  [0603]
R215  0  [0603]
R216  OPT  [0603]
R217  OPT  [1206]
R218  OPT  [0603]
R219  OPT  [0603]
R220  15.8k  [0603]
R221  OPT  [0603]
R222  0  [0603]
R223  4.99K  [0603]
R224  200  [0603]
R225  200  [0603]
U9  24LC025-I/ST  [TSSOP-8_4.4MM]

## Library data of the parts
C14-C17 C29-C41 C43 C45-C53 C74-C85 = CAP0603_1: Component: cap; Manufacturer: TDK; Manufacturer P/N: C1608C0G1H102J; Tolerance: 5%; Type: cer 0603; Vendor: Digikey; Vendor P/N: 445-1293-1-ND; Volts/Amps/Watts: 50V
CIN1 = CAPR12X5_0: Component: cap; Manufacturer: SANYO; Tolerance: 20%; Type: OS-CON; Volts/Amps/Watts: 16V
CIN2-CIN21 = CAP1210_1: Component: cap; Manufacturer: Taiyo Yuden; Manufacturer P/N: GMK325BJ106KN-T; Tolerance: 10%; Type: cer 1210; Vendor: Digikey; Vendor P/N: 587-1439-1-ND; Volts/Amps/Watts: 35V
COUT1 COUT65 COUT78 COUT90 = CAP0603_1: Component: cap; Manufacturer: TDK; Manufacturer P/N: C3225X5R0J107M; Tolerance: 20%; Type: cer 1210 X5R; Vendor: Digikey; Vendor P/N: 445-1437-1-ND; Volts/Amps/Watts: 6.3v
COUT2 COUT3 COUT6-COUT8 COUT46 COUT47 COUT49 COUT52 COUT53 COUT55 COUT58 COUT59 COUT62 COUT66 COUT67 COUT70 COUT71 COUT74 COUT77 COUT79 COUT82 COUT83 COUT86 COUT89 COUT91 COUT94-COUT99 = CAP0603_1: Component: cap; Manufacturer: TDK; Manufacturer P/N: C3225X5R0J107M; Part Type: CAP1210; Tolerance: 20%; Type: cer 1210 X5R; Vendor: Digikey; Vendor P/N: 445-1437-1-ND; Volts/Amps/Watts: 6.3v
COUT4 COUT11 COUT51 COUT57 COUT64 COUT68 COUT75 COUT80 COUT88 COUT92 = CAPR12X5_0: Component: cap; Manufacturer: SANYO; Manufacturer P/N: EEFGX0E471R; Tolerance: 20%; Type: SP-CAP; Volts/Amps/Watts: 2.5V
COUT5 COUT9 COUT10 COUT12 COUT48 COUT50 COUT54 COUT56 COUT60 COUT61 COUT63 COUT69 COUT72 COUT73 COUT76 COUT81 COUT84 COUT85 COUT87 COUT93 = CAPR12X5_0: Component: cap; Manufacturer: SANYO; Manufacturer P/N: EEFGX0E471R; Tolerance: 20%; Type: SP-CAP; Volts/Amps/Watts: 4V
E2 E5 = TURRETS_1: Component: tp; Manufacturer: Keystone; Manufacturer P/N: 1593-2; Vendor: Digikey; Vendor P/N: 1593-2K-ND
E3 E8 E16 E25 = TURRETS_1: Component: tp; Label: GND; Manufacturer: Keystone; Manufacturer P/N: 1593-2; Vendor: Digikey; Vendor P/N: 1593-2K-ND
E4 = TURRETS_1: Component: tp; Label: VIN; Manufacturer: Keystone; Manufacturer P/N: 1593-2; Vendor: Digikey; Vendor P/N: 1593-2K-ND
E6 = TURRETS_1: Component: tp; Label: SHARE_CLK; Manufacturer: Keystone; Manufacturer P/N: 1593-2; Vendor: Digikey; Vendor P/N: 1593-2K-ND
E9 = TURRETS_1: Component: tp; Label: SYNC; Manufacturer: Keystone; Manufacturer P/N: 1593-2; Vendor: Digikey; Vendor P/N: 1593-2K-ND
E10 = TURRETS_1: Component: tp; Label: ALERTB; Manufacturer: Keystone; Manufacturer P/N: 1593-2; Vendor: Digikey; Vendor P/N: 1593-2K-ND
E11 = TURRETS_1: Component: tp; Label: SCL; Manufacturer: Keystone; Manufacturer P/N: 1593-2; Vendor: Digikey; Vendor P/N: 1593-2K-ND
E12 = TURRETS_1: Component: tp; Label: SDA; Manufacturer: Keystone; Manufacturer P/N: 1593-2; Vendor: Digikey; Vendor P/N: 1593-2K-ND
E13 = TURRETS_1: Component: tp; Label: FAULT0; Manufacturer: Keystone; Manufacturer P/N: 1593-2; Vendor: Digikey; Vendor P/N: 1593-2K-ND
E15 = TURRETS_1: Component: tp; Label: VOUT_SNS; Vendor: Digikey; Vendor P/N: 1593-2K-ND
E17 = TURRETS_1: Component: tp; Label: GND_SNS; Vendor: Digikey; Vendor P/N: 1593-2K-ND
E26 = TURRETS_1: Component: tp; Label: PGOOD0; Manufacturer: Keystone; Manufacturer P/N: 1593-2; Vendor: Digikey; Vendor P/N: 1593-2K-ND
J7 J19 = BANANA_SMALL_0: Component: conn; Label: VOUT
J5 J8 J9 J20 = BANANA_SMALL_0: Component: conn; Label: GND
J10 = BANANA_SMALL_0: Component: conn; Label: VIN
P1-P17 = PAD_2: Component: tp; Label: <Label>; Vendor: Digikey; Vendor P/N: 1593-2K-ND
R8 R123 R158 R188 R231 R245 = RES0603_9: Label: OPT 0; Manufacturer: Rohm; Manufacturer P/N: RHM0.0GCT-ND; Vendor: Digikey
R9 R33 R127 R178 R196 R239 = RES0603_3
R10-R16 R18 R24 R29 R30 R91 R92 R95 R104-R107 R128-R131 R133-R152 R160 R162 R164 R166 R177 R179 R182 R183 R185-R187 R190-R192 R195 R197 R199 R200 R229 R230 R233-R235 R238 R240 R242 R243 = RES0603_9: Manufacturer: ROHM; Manufacturer P/N: MCR03EZPFX1002; Vendor: Digikey; Vendor P/N: RHM10.0KHCT-ND; Volts/Amps/Watts: 0.1W
R25 = RES0603_9: Manufacturer: Rohm; Manufacturer P/N: MCR03EZPFX1000; Vendor: Digikey; Vendor P/N: RHM100HCT-ND; Volts/Amps/Watts: 0.1W
R26 R27 R181 R184 R198 R201 R241 R244 = RES0603_9: Manufacturer: Panasonic; Manufacturer P/N: ERJ-3EKF2002V; Vendor: Digikey; Vendor P/N: P20.0KHCT-ND; Volts/Amps/Watts: 0.1W
R28 R159 R189 R232 = RES0603_9: Manufacturer: Panasonic; Manufacturer P/N: ERJ-3EKF1000V; Vendor: Digikey; Vendor P/N: P100HCT-ND; Volts/Amps/Watts: 0.1W
R31 R174 R194 R237 = RES0603_9: Manufacturer: Panasonic; Manufacturer P/N: ERJ-3EKF1021V; Vendor: Digikey; Vendor P/N: P1.02KHCT-ND; Volts/Amps/Watts: 0.1W
R32 = RES0603_9: Manufacturer: Yageo; Manufacturer P/N: RC0603JR-070RL; Tolerance: 5%; Vendor: Digikey; Vendor P/N: 311-0.0GRCT-ND; Volts/Amps/Watts: 0.1W
R90 R126 R153-R156 R173 R193 R236 = RES2512_0: Tolerance: <Tolerance>
SW0 = Commcon2802s03g2_7: 11th Part Field: OFF; 12th Part Field: RUN0; 9th Part Field: ON
U1-U5 = LTC3880-M0001_46: Component: IC; Manufacturer: LTC; Manufacturer P/N: LTC3880_M0001; Vendor: LTC; Vendor P/N: LTC3880_M0001
E1 = TURRETS_1: Component: tp; Label: VOUT1_SNS; Vendor: Digikey; Vendor P/N: 1593-2K-ND
E7 = TURRETS_1: Component: tp; Label: GND1_SNS; Vendor: Digikey; Vendor P/N: 1593-2K-ND
E14 = TURRETS_1: Component: tp; Label: FAULT1; Manufacturer: Keystone; Manufacturer P/N: 1593-2; Vendor: Digikey; Vendor P/N: 1593-2K-ND
E27 = TURRETS_1: Component: tp; Label: PGOOD1; Manufacturer: Keystone; Manufacturer P/N: 1593-2; Vendor: Digikey; Vendor P/N: 1593-2K-ND
J13 = BANANA_SMALL_0: Component: conn; Label: VOUT1
SW1 = Commcon2802s03g2_7: 11th Part Field: OFF; 12th Part Field: RUN 1; 9th Part Field: ON
C64 = CAP1206_1: Manufacturer: AVX; Tolerance: 10%; Type: cer 1206 X7R; Vendor: Digikey; Vendor P/N: 478-1567-1-ND; Volts/Amps/Watts: 25V
C65 C67 C68 = CAP1206_1: Manufacturer: AVX; Manufacturer P/N: 12063C105KAT2A; Tolerance: 10%; Type: cer 1206 X7R; Vendor: Digikey; Vendor P/N: 478-1567-1-ND; Volts/Amps/Watts: 25V
C66 = CAP1206_1: Manufacturer: Kemet; Manufacturer P/N: C1206C106K8RACTU; Tolerance: 10%; Type: cer 1206 X7R; Vendor: Digikey; Vendor P/N: 399-4937-1-ND; Volts/Amps/Watts: 10V
C69 = CAP0603_2: Component: cap; Manufacturer: TDK; Manufacturer P/N: C1608C0G1H102J; Tolerance: 5%; Type: cer 0603; Vendor: Digikey
C70 = CAP_NP_1: CAP, 0603 1.5nF 10% 50V X7R; Part Number: AVX 06033C152KAT
E23 = TURRETS_2: Label: EXT PULSE; Manufacturer: Keystone; Manufacturer P/N: 1593-2; Vendor: Digikey; Vendor P/N: 1593-2K-ND
E24 = TURRETS_2: Label: GND; Manufacturer: Keystone; Manufacturer P/N: 1593-2; Vendor: Digikey; Vendor P/N: 1593-2K-ND
J14 J15 = BNC5-SCH_0: CONN,BNC,5 PINS; Part Number: CONNEX 112404
JP1 JP2 = JP3X1_079_NO_12_2
Q11 Q12 = SUND50N03: XSTR, N-CHANNEL DMOS FET; 5TH PART FIELD: 2N7002TA
R102 = RES0603_5: Label: 1W; Manufacturer: VISHAY; Manufacturer P/N: CRCW251230R0JNEG; Tolerance: 5%; Vendor: Digikey; Vendor P/N: 541-30XCT-ND; Volts/Amps/Watts: 0.1W
R103 = RES0603_6: Label: 1W; Tolerance: 5%; Vendor: Digikey; Vendor P/N: 541-30XCT-ND; Volts/Amps/Watts: 0.1W
R108 R118 = RES0603_5: Label: 1W; Manufacturer: VISHAY; Manufacturer P/N: CRCW251230R0JNEG; Part Type: 2512; Tolerance: 5%; Vendor: Digikey; Vendor P/N: 541-30XCT-ND; Volts/Amps/Watts: 0.1W
R109 = RES0603_11
R110 = POT_A_0
R111-R117 R202-R205 R226-R228 = RES0603_9: Manufacturer: ROHM; Manufacturer P/N: MCR03EZPFX4991; Vendor: Digikey; Vendor P/N: RHM4.99KHCT-ND; Volts/Amps/Watts: 0.1w
U6 = LT1129CS8-3.3
U7 = LT1129CS8-3_0.3
U8 = LT1129CS8-3_3.3
C71 = CAP_NP: CAP, 0603 100nF 20% 16V X7R; Part Number: AVX 0603YC104MAT2A
C72 C73 = CAP_NP: CAP, 0603 10nF 10% 25V X7R; Part Number: AVX 06033C103KAT2A
D1 D2 D9 D10 = DIODE-LED_3: Manufacturer: PANASONIC; Manufacturer P/N: LN1371SGTRP
D3 = DIODE-LED_3: Label: GREEN; Manufacturer: PANASONIC
D4 D5 = DIODE_SCHOTTKY_9: DIODE, SCHOTTKY 30V, 100mA; Part Number: CENTRAL SEMI CMDSH-3-TR
D8 = DIODE_SCHOTTKY_0
E19 = TURRETS_2: Component: tp; Label: RUN0; Manufacturer: Keystone; Manufacturer P/N: 1593-2; Vendor: Digikey; Vendor P/N: 1593-2K-ND
E21 = TURRETS_2: Component: tp; Label: RUN1; Manufacturer: Keystone; Manufacturer P/N: 1593-2; Vendor: Digikey; Vendor P/N: 1593-2K-ND
E22 E29 = TURRETS_2: Component: tp; Label: GND; Manufacturer: Keystone; Manufacturer P/N: 1593-2; Vendor: Digikey; Vendor P/N: 1593-2K-ND
E28 = E_0: TURRET; Part Number: MILL MAX 2501-2-00-80-00-00-07-0
J12 = PMBUS_HEADER20_3: HEADER, 20PIN DUAL ROW R/A; Component: con; Manufacturer: Mill Max; Manufacturer P/N: 802-40-020-20-0001; Part Number: MILL MAX 802-40-020-20-0001; Type: header RA 20 dual row; Vendor: LTC; Vendor P/N: 802-40-020-20-001
J16 = HD2X6-079-PMBUS_2: HEADER, 12PIN 2mm STR DL; Label: DC1427A HEADER; Manufacturer: MOLEX; Manufacturer P/N: 87831-1220; Part Number: FCI 98414-G06-12ULF; Type: header 12POS 2MM VERT; Vendor: Digikey; Vendor P/N: WM18561-ND
J17 = PMBUS_CONNECTOR20_3: CONN, SOCKET 20PIN  DUAL ROW R/A; Component: con; Manufacturer: Mill Max; Manufacturer P/N: 803-93-020-20-001; Part Number: MILL MAX 803-93-020-20-001; Type: conn  RA 20 dual row; Vendor: LTC; Vendor P/N: 803-93-020-20-001
J18 = HD2X6-079-PMBUS_4: HEADER, 4PIN 2mm STR DL; Manufacturer: Hirose; Type: header 4POS 2MM VERT
Q2 = P-MOSFET: XSTR, N-CHANNEL DMOS FET
Q3 = TRANSISTOR_0: XSTR, N-CHANNEL DMOS FET
Q4 Q20 Q21 = TRANSISTOR_1: XSTR, N-CHANNEL DMOS FET
Q19 = P-MOSFET: XSTR, N-CHANNEL DMOS FET; Part Number: VISHAY TP0101K-T1-E3
R85 R86 R124 R224 R225 = RES0603_9: Label: OPT 0; Manufacturer: Rohm; Manufacturer P/N: RHM0.0GCT-ND; Tolerance: 5%; Vendor: Digikey; Vendor P/N: RHM0.0GCT-ND; Volts/Amps/Watts: 0.1W
R125 R209 = RES0603_1: RES, 0603 10 OHMS 5% 1/10W; Manufacturer: Rohm; Manufacturer P/N: RHM0.0GCT-ND; Part Number: VISHAY CRCW060310R0JNEA; Tolerance: 5%; Vendor: Digikey; Vendor P/N: RHM0.0GCT-ND; Volts/Amps/Watts: 0.1W
R132 R206 R212 R216 R218 R219 R221 = RES0603_0: RES, 0603 OPTION; Label: OPT 0; Manufacturer: Rohm; Manufacturer P/N: RHM0.0GCT-ND; Part Number: OPTION; Tolerance: 5%; Vendor: Digikey; Vendor P/N: RHM0.0GCT-ND; Volts/Amps/Watts: 0.1W
R207 R214 R215 R222 = RES0603_0: RES, 0603 0 OHMS JUMPER; Label: OPT 0; Manufacturer: Rohm; Manufacturer P/N: RHM0.0GCT-ND; Part Number: VISHAY CRCW06030000Z0EA; Tolerance: 5%; Vendor: Digikey; Vendor P/N: RHM0.0GCT-ND; Volts/Amps/Watts: 0.1W
R208 R217 = RES0603_3: RES, 0603 OPTION; Label: OPT 0; Manufacturer: Rohm; Manufacturer P/N: RHM0.0GCT-ND; Part Number: OPTION; Tolerance: 5%; Vendor: Digikey; Vendor P/N: RHM0.0GCT-ND; Volts/Amps/Watts: 0.1W
R210 = RES0603_11: RES, 0603 10K OHMS 5% 1/10W; Part Number: VISHAY CRCW060310K0JNEA
R211 = RES0603_0: RES, 0603 0 OHMS JUMPER; Manufacturer: Rohm; Manufacturer P/N: RHM0.0GCT-ND; Part Number: VISHAY CRCW06030000Z0EA; Tolerance: 5%; Vendor: Digikey; Vendor P/N: RHM0.0GCT-ND; Volts/Amps/Watts: 0.1W
R213 R223 = RES0603_0: RES, 0603 4.99K OHMS 1% 1/10W; Manufacturer: ROHM; Manufacturer P/N: MCR03EZPFX4991; Part Number: VISHAY CRCW06034K99FKEA; Vendor: Digikey; Vendor P/N: RHM4.99KHCT-ND; Volts/Amps/Watts: 0.1w
R220 = RES0603_11: RES, 0603 15.8K OHMS 1% 1/10W; Part Number: VISHAY CRCW060315K8FKEA
U9 = 24LC025-I_SN: IC, 24LC05-I/ST; Part Number: MICROCHIP 24LC025-I/ST

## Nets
3V3: J16.5(LGKPWR) Q2.2(S) Q19.3(D) R85.1 R124.1 R221.1 R224.1 R225.1
+5.5V: C64.1 C68.1 R123.1 R202.2 R227.2 R228.2 U6.1(OUTPUT)
GND_POWER: C30.1 C31.2 C32.2 C34.2 C36.2 C41.1 C45.2 C47.2 C49.1 C51.2 C53.2 C64.2 C65.2 C66.2 C70.1 C71.2 C72.2 C73.2 C75.1 C77.2 C79.2 C80.2 C81.2 C82.2 C83.2 C84.2 C85.1 CIN1.2 CIN2.2 CIN3.2 CIN4.2 CIN5.2 CIN6.2 CIN7.2 CIN8.2 CIN9.2 CIN10.2 CIN11.2 CIN12.2 CIN13.2 CIN14.2 CIN15.2 CIN16.2 CIN17.2 CIN18.2 CIN19.2 CIN20.2 CIN21.2 COUT1.2 COUT2.2 COUT3.2 COUT4.2 COUT5.2 COUT6.2 COUT7.2 COUT8.2 COUT9.2 COUT10.2 COUT11.2 COUT12.2 COUT46.2 COUT47.2 COUT48.2 COUT49.2 COUT50.2 COUT51.2 COUT52.2 COUT53.2 COUT54.2 COUT55.2 COUT56.2 COUT57.2 COUT58.2 COUT59.2 COUT60.2 COUT61.2 COUT62.2 COUT63.2 COUT64.2 COUT65.2 COUT66.2 COUT67.2 COUT68.2 COUT69.2 COUT70.2 COUT71.2 COUT72.2 COUT73.2 COUT74.2 COUT75.2 COUT76.2 COUT77.2 COUT78.2 COUT79.2 COUT80.2 COUT81.2 COUT82.2 COUT83.2 COUT84.2 COUT85.2 COUT86.2 COUT87.2 COUT88.2 COUT89.2 COUT90.2 COUT91.2 COUT92.2 COUT93.2 COUT94.2 COUT95.2 COUT96.2 COUT97.2 COUT98.2 COUT99.2 E2.1(TP) E5.1(TP) E24.1(TP) J5.1(TP) J8.1(TP) J9.1(TP) J12.11(GND) J12.12(GND) J14.2 J14.3 J14.4 J14.5 J15.2 J15.3 J15.4 J15.5 J16.3(GND) J16.10(GND) J17.11(GND) J17.12(GND) J18.2(GND) J20.1(TP) JP1.1 R32.2 R33.1 R102.1 R103.1 R108.1 R116.2 R118.1 R133.1 R220.2 R226.2 R245.2 U1.A3(GND) U1.A4(GND) U1.A5(GND) U1.A6(GND) U1.B1(GND) U1.B3(GND) U1.B4(GND) U1.B5(GND) U1.B6(GND) U1.C1(GND) U1.C2(GND) U1.C3(GND) U1.C4(GND) U1.C5(GND) U1.C6(GND) U1.D2(GND) U1.D3(GND) U1.D4(GND) U1.D5(GND) U1.D6(GND) U1.E5(GND) U1.E6(GND) U1.F5(GND) U1.F6(GND) U1.F7(GND) U1.G5(GND) U1.G6(GND) U1.G7(GND) U1.G8(GND) U1.H5(GND) U1.H6(GND) U1.H7(GND) U1.H8(GND) U1.J2(GND) U1.J3(GND) U1.J4(GND) U1.J5(GND) U1.J6(GND) U1.K2(GND) U1.K3(GND) U1.K4(GND) U1.K5(GND) U1.K6(GND) U1.L1(GND) U1.L3(GND) U1.L4(GND) U1.L5(GND) U1.L6(GND) U1.M3(GND) U1.M4(GND) U1.M5(GND) U1.M6(GND) U2.A3(GND) U2.A4(GND) U2.A5(GND) U2.A6(GND) U2.B1(GND) U2.B3(GND) U2.B4(GND) U2.B5(GND) U2.B6(GND) U2.C1(GND) U2.C2(GND) U2.C3(GND) U2.C4(GND) U2.C5(GND) U2.C6(GND) U2.D2(GND) U2.D3(GND) U2.D4(GND) U2.D5(GND) U2.D6(GND) U2.E5(GND) U2.E6(GND) U2.F5(GND) U2.F6(GND) U2.F7(GND) U2.G5(GND) U2.G6(GND) U2.G7(GND) U2.G8(GND) U2.H5(GND) U2.H6(GND) U2.H7(GND) U2.H8(GND) U2.J2(GND) U2.J3(GND) U2.J4(GND) U2.J5(GND) U2.J6(GND) U2.K2(GND) U2.K3(GND) U2.K4(GND) U2.K5(GND) U2.K6(GND) U2.L1(GND) U2.L3(GND) U2.L4(GND) U2.L5(GND) U2.L6(GND) U2.M3(GND) U2.M4(GND) U2.M5(GND) U2.M6(GND) U3.A3(GND) U3.A4(GND) U3.A5(GND) U3.A6(GND) U3.B1(GND) U3.B3(GND) U3.B4(GND) U3.B5(GND) U3.B6(GND) U3.C1(GND) U3.C2(GND) U3.C3(GND) U3.C4(GND) U3.C5(GND) U3.C6(GND) U3.D2(GND) U3.D3(GND) U3.D4(GND) U3.D5(GND) U3.D6(GND) U3.E5(GND) U3.E6(GND) U3.F5(GND) U3.F6(GND) U3.F7(GND) U3.G5(GND) U3.G6(GND) U3.G7(GND) U3.G8(GND) U3.H5(GND) U3.H6(GND) U3.H7(GND) U3.H8(GND) U3.J2(GND) U3.J3(GND) U3.J4(GND) U3.J5(GND) U3.J6(GND) U3.K2(GND) U3.K3(GND) U3.K4(GND) U3.K5(GND) U3.K6(GND) U3.L1(GND) U3.L3(GND) U3.L4(GND) U3.L5(GND) U3.L6(GND) U3.M3(GND) U3.M4(GND) U3.M5(GND) U3.M6(GND) U4.A3(GND) U4.A4(GND) U4.A5(GND) U4.A6(GND) U4.B1(GND) U4.B3(GND) U4.B4(GND) U4.B5(GND) U4.B6(GND) U4.C1(GND) U4.C2(GND) U4.C3(GND) U4.C4(GND) U4.C5(GND) U4.C6(GND) U4.D2(GND) U4.D3(GND) U4.D4(GND) U4.D5(GND) U4.D6(GND) U4.E5(GND) U4.E6(GND) U4.F5(GND) U4.F6(GND) U4.F7(GND) U4.G5(GND) U4.G6(GND) U4.G7(GND) U4.G8(GND) U4.H5(GND) U4.H6(GND) U4.H7(GND) U4.H8(GND) U4.J2(GND) U4.J3(GND) U4.J4(GND) U4.J5(GND) U4.J6(GND) U4.K2(GND) U4.K3(GND) U4.K4(GND) U4.K5(GND) U4.K6(GND) U4.L1(GND) U4.L3(GND) U4.L4(GND) U4.L5(GND) U4.L6(GND) U4.M3(GND) U4.M4(GND) U4.M5(GND) U4.M6(GND) U5.A3(GND) U5.A4(GND) U5.A5(GND) U5.A6(GND) U5.B1(GND) U5.B3(GND) U5.B4(GND) U5.B5(GND) U5.B6(GND) U5.C1(GND) U5.C2(GND) U5.C3(GND) U5.C4(GND) U5.C5(GND) U5.C6(GND) U5.D2(GND) U5.D3(GND) U5.D4(GND) U5.D5(GND) U5.D6(GND) U5.E5(GND) U5.E6(GND) U5.F5(GND) U5.F6(GND) U5.F7(GND) U5.G5(GND) U5.G6(GND) U5.G7(GND) U5.G8(GND) U5.H5(GND) U5.H6(GND) U5.H7(GND) U5.H8(GND) U5.J2(GND) U5.J3(GND) U5.J4(GND) U5.J5(GND) U5.J6(GND) U5.K2(GND) U5.K3(GND) U5.K4(GND) U5.K5(GND) U5.K6(GND) U5.L1(GND) U5.L3(GND) U5.L4(GND) U5.L5(GND) U5.L6(GND) U5.M3(GND) U5.M4(GND) U5.M5(GND) U5.M6(GND) U6.3(GND) U6.6(GND) U6.7(GND) U9.1(A0) U9.2(A1) U9.3(A2) U9.4(VSS) U9.7(WP)
GND_SIGNAL: C14.2 C15.2 C37.1 C38.1 C67.2 C68.2 E22.1(TP) E29.1(TP) Q3.2(S) Q4.2(S) Q20.2(S) Q21.2(S) R24.1 R26.1 R27.1 R28.1 R29.1 R30.1 R31.1 R33.2 R86.2 R110.1 R110.2 R113.2 R115.2 R139.1 R140.1 R141.1 R142.1 R143.1 R144.1 R145.2 R159.1 R160.1 R162.1 R166.1 R174.1 R181.1 R184.1 R189.1 R190.1 R191.1 R192.1 R194.1 R198.1 R201.1 R203.2 R232.1 R233.1 R234.1 R235.1 R237.1 R241.1 R244.1 SW0.3 SW1.3 U1.F9(SGND) U1.F10(SGND) U1.G9(SGND) U1.G10(SGND) U2.F9(SGND) U2.F10(SGND) U2.G9(SGND) U2.G10(SGND) U3.F9(SGND) U3.F10(SGND) U3.G9(SGND) U3.G10(SGND) U4.F9(SGND) U4.F10(SGND) U4.G9(SGND) U4.G10(SGND) U5.F9(SGND) U5.F10(SGND) U5.G9(SGND) U5.G10(SGND) U7.2(GND) U8.2(V-)
VDD25: E16.1(TP) U1.D12(VDD25)
VDD33: D8.1(CATHODE) E8.1(TP) Q19.2(S) R10.1 R11.1 R12.1 R13.1 R14.1 R15.1 R16.1 R18.1 R95.1 U1.E8(VDD33)
VIN: C65.1 CIN1.1 E4.1(TP) J10.1(TP) R8.1 R9.1 R90.1 R91.1 R109.1 R126.1 R127.1 R128.1 R135.1 R158.1 R173.1 R177.1 R178.1 R188.1 R193.1 R195.1 R196.1 R210.1 R217.1 R231.1 R236.1 R238.1 R239.1 U6.8(VIN)
VIN1: CIN2.1 CIN3.1 CIN4.1 CIN5.1 R90.2 R92.1 U1.E1(VIN1) U1.E2(VIN1) U1.E3(VIN1) U1.E4(VIN1) U1.F1(VIN1) U1.F2(VIN1) U1.F3(VIN1) U1.F4(VIN1) U1.G1(VIN0) U1.G2(VIN0) U1.G3(VIN0) U1.G4(VIN0) U1.H1(VIN0) U1.H2(VIN0) U1.H3(VIN0) U1.H4(VIN0)
VIN2: CIN6.1 CIN7.1 CIN8.1 CIN9.1 R126.2 R129.1 U2.E1(VIN1) U2.E2(VIN1) U2.E3(VIN1) U2.E4(VIN1) U2.F1(VIN1) U2.F2(VIN1) U2.F3(VIN1) U2.F4(VIN1) U2.G1(VIN0) U2.G2(VIN0) U2.G3(VIN0) U2.G4(VIN0) U2.H1(VIN0) U2.H2(VIN0) U2.H3(VIN0) U2.H4(VIN0)
VIN3: CIN10.1 CIN11.1 CIN12.1 CIN13.1 R173.2 R179.1 U3.E1(VIN1) U3.E2(VIN1) U3.E3(VIN1) U3.E4(VIN1) U3.F1(VIN1) U3.F2(VIN1) U3.F3(VIN1) U3.F4(VIN1) U3.G1(VIN0) U3.G2(VIN0) U3.G3(VIN0) U3.G4(VIN0) U3.H1(VIN0) U3.H2(VIN0) U3.H3(VIN0) U3.H4(VIN0)
VIN4: CIN14.1 CIN15.1 CIN16.1 CIN17.1 R193.2 R197.1 U4.E1(VIN1) U4.E2(VIN1) U4.E3(VIN1) U4.E4(VIN1) U4.F1(VIN1) U4.F2(VIN1) U4.F3(VIN1) U4.F4(VIN1) U4.G1(VIN0) U4.G2(VIN0) U4.G3(VIN0) U4.G4(VIN0) U4.H1(VIN0) U4.H2(VIN0) U4.H3(VIN0) U4.H4(VIN0)
VIN5: CIN18.1 CIN19.1 CIN20.1 CIN21.1 R236.2 R240.1 U5.E1(VIN1) U5.E2(VIN1) U5.E3(VIN1) U5.E4(VIN1) U5.F1(VIN1) U5.F2(VIN1) U5.F3(VIN1) U5.F4(VIN1) U5.G1(VIN0) U5.G2(VIN0) U5.G3(VIN0) U5.G4(VIN0) U5.H1(VIN0) U5.H2(VIN0) U5.H3(VIN0) U5.H4(VIN0)
ALERTB: E10.1(TP) J12.3(ALERTB) J16.6(ALERTB) J17.3(ALERTB) Q2.1(G) R12.2 U1.H11(~{ALERT}) U2.H11(~{ALERT}) U3.H11(~{ALERT}) U4.H11(~{ALERT}) U5.H11(~{ALERT})
AUX3V4: D8.2(ANODE) J18.4(AUX3V4)
AUXVCC: C71.1 E28.1(A) J12.8(AUXP) J16.1(AUXP) J17.8(AUXP) R213.1 R223.1 U9.8(VCC)
COMP1a: C37.2 R148.1 U2.D10(COMP1a)
COMP1b: C38.2 R149.1 U2.C10(COMP1b)
COMPa: C14.1 R148.2 U1.D10(COMP1a) U1.J9(COMP0a) U2.J9(COMP0a) U3.D10(COMP1a) U3.J9(COMP0a) U4.D10(COMP1a) U4.J9(COMP0a) U5.D10(COMP1a) U5.J9(COMP0a)
COMPb: C15.1 R149.2 U1.C10(COMP1b) U1.H9(COMP0b) U2.H9(COMP0b) U3.C10(COMP1b) U3.H9(COMP0b) U4.C10(COMP1b) U4.H9(COMP0b) U5.C10(COMP1b) U5.H9(COMP0b)
EESCL: J16.11(AUXSCL) R213.2 U9.6(SCL)
EESDA: J16.12(AUXSDA) R223.2 U9.5(SDA)
EXTVCC: C30.2 C41.2 C49.2 C75.2 C85.2 E25.1(TP) R228.1 R245.1 U1.F8(EXTVCC) U2.F8(EXTVCC) U3.F8(EXTVCC) U4.F8(EXTVCC) U5.F8(EXTVCC)
FAULT0: D5.2(ANODE) E13.1(TP) Q3.1(G) R15.2 R107.1 R146.2 R185.2 R186.2 R206.2 R215.2 R229.2 U1.H12(~{FAULT0}) U2.H12(~{FAULT0}) U3.H12(~{FAULT0}) U4.H12(~{FAULT0}) U5.H12(~{FAULT0})
FAULT1: D4.2(ANODE) E14.1(TP) Q4.1(G) R136.2 R146.1 R212.2 R214.2 U2.G11(~{FAULT1})
INTVCC: C80.1 E3.1(TP) R8.2 U1.E7(INTVCC)
PGOOD0: E26.1(TP) Q20.1(G) R18.2 R106.1 R150.2 R164.2 R187.2 R230.2 U1.J7(PGOOD0) U2.J7(PGOOD0) U3.J7(PGOOD0) U4.J7(PGOOD0) U5.J7(PGOOD0)
PGOOD1: E27.1(TP) Q21.1(G) R138.2 R150.1 U2.D9(PGOOD1)
RUN0: D5.1(CATHODE) E19.1(TP) R125.2 R147.1 R212.1 R218.2 R222.2 SW0.2 U1.F11(RUN1) U1.G12(RUN0) U2.G12(RUN0) U3.F11(RUN1) U3.G12(RUN0) U4.F11(RUN1) U4.G12(RUN0) U5.F11(RUN1) U5.G12(RUN0)
RUN1: D4.1(CATHODE) E21.1(TP) R132.2 R147.2 R206.1 R207.2 R209.2 SW1.2 U2.F11(RUN1)
SCL: E11.1(TP) J12.6(SCL) J16.4(SCL) J17.6(SCL) J18.3(SCL) R13.2 U1.J12(SCL) U2.J12(SCL) U3.J12(SCL) U4.J12(SCL) U5.J12(SCL)
SDA: E12.1(TP) J12.4(SDA) J16.2(SDA) J17.4(SDA) J18.1(SDA) R14.2 U1.H10(SDA) U2.H10(SDA) U3.H10(SDA) U4.H10(SDA) U5.H10(SDA)
SHARE_CLK: E6.1(TP) R11.2 R211.1 U1.D11(SHARE_CLK) U2.D11(SHARE_CLK) U3.D11(SHARE_CLK) U4.D11(SHARE_CLK) U5.D11(SHARE_CLK)
SYNC: E9.1(TP) R10.2 R219.1 U1.K12(SYNC) U2.K12(SYNC) U3.K12(SYNC) U4.K12(SYNC) U5.K12(SYNC)
VOSNS1+: C39.1 E1.1(TP) R134.2 R151.1 U2.A11(VOSNS1+)
VOSNS1-: C39.2 E7.1(TP) R133.2 R152.1 U2.A12(VOSNS1-)
VOSNS+: C16.1 C17.1 C35.1 C40.1 C46.1 C48.1 C52.1 C74.1 C78.1 E15.1(TP) R25.1 R151.2 U1.A11(VOSNS1+) U1.M11(VOSNS0+) U2.M11(VOSNS0+) U3.A11(VOSNS1+) U3.M11(VOSNS0+) U4.A11(VOSNS1+) U4.M11(VOSNS0+) U5.A11(VOSNS1+) U5.M11(VOSNS0+)
VOSNS-: C16.2 C17.2 C35.2 C40.2 C46.2 C48.2 C52.2 C74.2 C78.2 E17.1(TP) R32.1 R152.2 U1.A12(VOSNS1-) U1.M12(VOSNS0-) U2.M12(VOSNS0-) U3.A12(VOSNS1-) U3.M12(VOSNS0-) U4.A12(VOSNS1-) U4.M12(VOSNS0-) U5.A12(VOSNS1-) U5.M12(VOSNS0-)
VOUT: C66.1 COUT1.1 COUT2.1 COUT3.1 COUT4.1 COUT5.1 COUT6.1 COUT7.1 COUT8.1 COUT9.1 COUT10.1 COUT11.1 COUT12.1 COUT46.1 COUT47.1 COUT48.1 COUT49.1 COUT50.1 COUT51.1 COUT58.1 COUT59.1 COUT60.1 COUT61.1 COUT62.1 COUT63.1 COUT64.1 COUT65.1 COUT66.1 COUT67.1 COUT68.1 COUT69.1 COUT70.1 COUT71.1 COUT72.1 COUT73.1 COUT74.1 COUT75.1 COUT76.1 COUT77.1 COUT78.1 COUT79.1 COUT80.1 COUT81.1 COUT82.1 COUT83.1 COUT84.1 COUT85.1 COUT86.1 COUT87.1 COUT88.1 COUT89.1 COUT90.1 COUT91.1 COUT92.1 COUT93.1 COUT94.1 COUT95.1 COUT96.1 COUT97.1 COUT98.1 COUT99.1 J7.1(TP) J15.1 J19.1(TP) Q11.3 Q12.3 R25.2 R102.2 R153.1 R154.1 R155.1 R156.1 U1.A7(VOUT1) U1.A8(VOUT1) U1.A9(VOUT1) U1.A10(VOUT1) U1.B7(VOUT1) U1.B8(VOUT1) U1.B9(VOUT1) U1.B10(VOUT1) U1.B11(VOUT1) U1.B12(VOUT1) U1.C7(VOUT1) U1.C8(VOUT1) U1.C9(VOUT1) U1.D7(VOUT1) U1.K7(VOUT0) U1.K8(VOUT0) U1.K9(VOUT0) U1.K10(VOUT0) U1.K11(VOUT0) U1.L7(VOUT0) U1.L8(VOUT0) U1.L9(VOUT0) U1.L10(VOUT0) U1.L11(VOUT0) U1.L12(VOUT0) U1.M7(VOUT0) U1.M8(VOUT0) U1.M9(VOUT0) U1.M10(VOUT0) U2.K7(VOUT0) U2.K8(VOUT0) U2.K9(VOUT0) U2.K10(VOUT0) U2.K11(VOUT0) U2.L7(VOUT0) U2.L8(VOUT0) U2.L9(VOUT0) U2.L10(VOUT0) U2.L11(VOUT0) U2.L12(VOUT0) U2.M7(VOUT0) U2.M8(VOUT0) U2.M9(VOUT0) U2.M10(VOUT0) U3.A7(VOUT1) U3.A8(VOUT1) U3.A9(VOUT1) U3.A10(VOUT1) U3.B7(VOUT1) U3.B8(VOUT1) U3.B9(VOUT1) U3.B10(VOUT1) U3.B11(VOUT1) U3.B12(VOUT1) U3.C7(VOUT1) U3.C8(VOUT1) U3.C9(VOUT1) U3.D7(VOUT1) U3.K7(VOUT0) U3.K8(VOUT0) U3.K9(VOUT0) U3.K10(VOUT0) U3.K11(VOUT0) U3.L7(VOUT0) U3.L8(VOUT0) U3.L9(VOUT0) U3.L10(VOUT0) U3.L11(VOUT0) U3.L12(VOUT0) U3.M7(VOUT0) U3.M8(VOUT0) U3.M9(VOUT0) U3.M10(VOUT0) U4.A7(VOUT1) U4.A8(VOUT1) U4.A9(VOUT1) U4.A10(VOUT1) U4.B7(VOUT1) U4.B8(VOUT1) U4.B9(VOUT1) U4.B10(VOUT1) U4.B11(VOUT1) U4.B12(VOUT1) U4.C7(VOUT1) U4.C8(VOUT1) U4.C9(VOUT1) U4.D7(VOUT1) U4.K7(VOUT0) U4.K8(VOUT0) U4.K9(VOUT0) U4.K10(VOUT0) U4.K11(VOUT0) U4.L7(VOUT0) U4.L8(VOUT0) U4.L9(VOUT0) U4.L10(VOUT0) U4.L11(VOUT0) U4.L12(VOUT0) U4.M7(VOUT0) U4.M8(VOUT0) U4.M9(VOUT0) U4.M10(VOUT0) U5.A7(VOUT1) U5.A8(VOUT1) U5.A9(VOUT1) U5.A10(VOUT1) U5.B7(VOUT1) U5.B8(VOUT1) U5.B9(VOUT1) U5.B10(VOUT1) U5.B11(VOUT1) U5.B12(VOUT1) U5.C7(VOUT1) U5.C8(VOUT1) U5.C9(VOUT1) U5.D7(VOUT1) U5.K7(VOUT0) U5.K8(VOUT0) U5.K9(VOUT0) U5.K10(VOUT0) U5.K11(VOUT0) U5.L7(VOUT0) U5.L8(VOUT0) U5.L9(VOUT0) U5.L10(VOUT0) U5.L11(VOUT0) U5.L12(VOUT0) U5.M7(VOUT0) U5.M8(VOUT0) U5.M9(VOUT0) U5.M10(VOUT0)
VOUT1: COUT52.1 COUT53.1 COUT54.1 COUT55.1 COUT56.1 COUT57.1 J13.1(TP) R103.2 R134.1 R153.2 R154.2 R155.2 R156.2 U2.A7(VOUT1) U2.A8(VOUT1) U2.A9(VOUT1) U2.A10(VOUT1) U2.B7(VOUT1) U2.B8(VOUT1) U2.B9(VOUT1) U2.B10(VOUT1) U2.B11(VOUT1) U2.B12(VOUT1) U2.C7(VOUT1) U2.C8(VOUT1) U2.C9(VOUT1) U2.D7(VOUT1)
N16992964: R9.2 U1.D1(SVIN)
N17166430: P1.1(TP) R105.2 U1.A1(SW1) U1.A2(SW1) U1.B2(SW1)
N17205156: R16.2 R107.2 U1.G11(~{FAULT1})
N17222714: R26.2 U1.F12(ASEL)
N17223298: R27.2 U1.E9(FSWPH_CFG)
N17223884: R28.2 U1.E10(VTRIM1_CFG)
N17224472: R29.2 U1.C12(VTRIM0_CFG)
N17225062: R30.2 U1.E11(VOUT0CFG)
N17225654: R31.2 U1.E12(VOUT1CFG)
N18377351: U1.D8(TSNS1B) U1.J10(TSNS1A)
N18377392: U1.J8(TSNS0B) U1.J11(TSNS0A)
N18440006: C29.1 R91.2 U1.J1(IN+)
N18440037: C29.2 R92.2 U1.K1(IN-)
N18440925: P2.1(TP) R104.2 U1.L2(SW0) U1.M1(SW0) U1.M2(SW0)
N18449385: R24.2 U1.C11(WP)
N18449487: R106.2 U1.D9(PGOOD1)
N18450817: R95.2 SW0.1
N18468612: C31.1 R104.1
N18469531: C32.1 R105.1
N18485910: R136.1 R137.1 R138.1 U2.E8(VDD33)
N18486455: R137.2 SW1.1
N18486616: C81.1 R135.2 U2.E7(INTVCC)
N18486630: U2.D8(TSNS1B) U2.J10(TSNS1A)
N18486737: P4.1(TP) R131.1 U2.A1(SW1) U2.A2(SW1) U2.B2(SW1)
N18486824: R145.1 U2.C11(WP)
N18487003: R139.2 U2.F12(ASEL)
N18487036: R140.2 U2.E9(FSWPH_CFG)
N18487072: R141.2 U2.E10(VTRIM1_CFG)
N18487104: R142.2 U2.C12(VTRIM0_CFG)
N18487145: R143.2 U2.E11(VOUT0CFG)
N18487175: R144.2 U2.E12(VOUT1CFG)
N18488778: R127.2 U2.D1(SVIN)
N18489333: C33.1 R128.2 U2.J1(IN+)
N18489335: C33.2 R129.2 U2.K1(IN-)
N18489469: P3.1(TP) R130.2 U2.L2(SW0) U2.M1(SW0) U2.M2(SW0)
N18489496: U2.J8(TSNS0B) U2.J11(TSNS0A)
N18489561: C34.1 R130.1
N18491686: C36.1 R131.2
N18506549: C83.1 R158.2 U3.E7(INTVCC)
N18506589: P8.1(TP) U3.E8(VDD33)
N18506681: R185.1 U3.G11(~{FAULT1})
N18506689: P5.1(TP) R183.2 U3.A1(SW1) U3.A2(SW1) U3.B2(SW1)
N18506850: R162.2 U3.C11(WP)
N18506870: R164.1 U3.D9(PGOOD1)
N18507036: P6.1(TP) R182.2 U3.L2(SW0) U3.M1(SW0) U3.M2(SW0)
N18507317: R181.2 U3.F12(ASEL)
N18507360: C43.1 R177.2 U3.J1(IN+)
N18507362: R184.2 U3.E9(FSWPH_CFG)
N18507364: C43.2 R179.2 U3.K1(IN-)
N18507600: R159.2 U3.E10(VTRIM1_CFG)
N18507796: R160.2 U3.C12(VTRIM0_CFG)
N18507850: R166.2 U3.E11(VOUT0CFG)
N18507864: U3.D8(TSNS1B) U3.J10(TSNS1A)
N18507872: U3.J8(TSNS0B) U3.J11(TSNS0A)
N18507906: R174.2 U3.E12(VOUT1CFG)
N18507917: R178.2 U3.D1(SVIN)
N18507929: C45.1 R182.1
N18508036: C47.1 R183.1
N18513572: P9.1(TP) U3.D12(VDD25)
N18514884: P11.1(TP) U4.D12(VDD25)
N18514926: C82.1 R188.2 U4.E7(INTVCC)
N18514952: P10.1(TP) U4.E8(VDD33)
N18515022: R186.1 U4.G11(~{FAULT1})
N18515036: P12.1(TP) R200.2 U4.A1(SW1) U4.A2(SW1) U4.B2(SW1)
N18515142: R191.2 U4.C11(WP)
N18515152: R187.1 U4.D9(PGOOD1)
N18515198: P13.1(TP) R199.2 U4.L2(SW0) U4.M1(SW0) U4.M2(SW0)
N18515300: R198.2 U4.F12(ASEL)
N18515335: C50.1 R195.2 U4.J1(IN+)
N18515337: R201.2 U4.E9(FSWPH_CFG)
N18515339: C50.2 R197.2 U4.K1(IN-)
N18515535: R189.2 U4.E10(VTRIM1_CFG)
N18515697: R190.2 U4.C12(VTRIM0_CFG)
N18515731: R192.2 U4.E11(VOUT0CFG)
N18515745: U4.D8(TSNS1B) U4.J10(TSNS1A)
N18515753: U4.J8(TSNS0B) U4.J11(TSNS0A)
N18515765: R194.2 U4.E12(VOUT1CFG)
N18515767: R196.2 U4.D1(SVIN)
N18515772: C51.1 R199.1
N18515856: C53.1 R200.1
N18517055: JP2.1 R204.2
N18517059: JP2.2 JP2.3 Q11.1 Q12.1 R116.1 R117.2
N18517067: E23.1(TP) R117.1
N18517069: C70.2 J14.1 Q11.2 Q12.2 R108.2 R118.2 R205.2
N18517088: JP1.2 R109.2 U6.5(~{SHDN})
N18517235: R123.2 R203.1 U7.4(DIV)
N18517369: C67.1 R111.1 U7.6(OUT) U8.5(V+)
N18517437: R202.1 U7.5(V+)
N18517576: R110.3 R112.2 R113.1
N18517602: C69.1 R204.1 U8.1(VOUT)
N18517616: R111.2 R112.1 U8.3(+IN)
N18517618: C69.2 R205.1 U8.4(-IN)
N18517698: R114.2 U7.3(SET)
N18517700: R114.1 R115.1 U7.1(MOD)
N18520598: J16.8(OUTEN_0) R208.1
N18520602: C72.1 R209.1
N18520604: C73.1 R125.1
N18520626: Q19.1(G) R210.2 R220.1
N18520652: J12.2(CTRL) J17.2(CTRL) R207.1 R208.2 R216.2 R222.1
N18520656: J12.5(SHARE_CLK) J17.5(SHARE_CLK) R211.2
N18520658: J12.7(RESETB) J17.7(RESETB)
N18520660: J12.9(UNUSED) J17.9(UNUSED) R132.1 R218.1 R219.2
N18520672: J12.13(12V) J12.14(12V) J17.13(12V) J17.14(12V) R217.2
N18520704: J12.1(FAULTB) J17.1(FAULTB) R214.1 R215.1
N18520744: J12.10(UNUSED) J17.10(UNUSED) R221.2
N18521305: D2.1(A) R124.2
N18521307: D2.2(K) Q3.3(D)
N18521313: D1.2(K) Q4.3(D)
N18521317: D3.1(A) Q2.3(D)
N18521325: D3.2(K) R86.1
N18521615: J16.9(OUTEN_1) R216.1
N18522532: D9.2(K) Q20.3(D)
N18522661: D10.2(K) Q21.3(D)
N18528429: R226.1 R227.1 U6.2(SENSE/ADJ)
N18535484: P15.1(TP) U5.D12(VDD25)
N18535522: C84.1 R231.2 U5.E7(INTVCC)
N18535544: P14.1(TP) U5.E8(VDD33)
N18535612: R229.1 U5.G11(~{FAULT1})
N18535626: P16.1(TP) R243.2 U5.A1(SW1) U5.A2(SW1) U5.B2(SW1)
N18535738: R234.2 U5.C11(WP)
N18535752: R230.1 U5.D9(PGOOD1)
N18535796: P17.1(TP) R242.2 U5.L2(SW0) U5.M1(SW0) U5.M2(SW0)
N18535896: R241.2 U5.F12(ASEL)
N18535928: C76.1 R238.2 U5.J1(IN+)
N18535930: R244.2 U5.E9(FSWPH_CFG)
N18535932: C76.2 R240.2 U5.K1(IN-)
N18535983: R232.2 U5.E10(VTRIM1_CFG)
N18536297: R233.2 U5.C12(VTRIM0_CFG)
N18536331: R235.2 U5.E11(VOUT0CFG)
N18536345: U5.D8(TSNS1B) U5.J10(TSNS1A)
N18536353: U5.J8(TSNS0B) U5.J11(TSNS0A)
N18536365: R237.2 U5.E12(VOUT1CFG)
N18536367: R239.2 U5.D1(SVIN)
N18536369: C77.1 R242.1
N18536456: C79.1 R243.1
N18630078: D10.1(A) R225.2
N18630079: D9.1(A) R224.2
N18630080: D1.1(A) R85.2
N18664800: P7.1(TP) U2.D12(VDD25)

Not connected (* = marked no-connect by the designer): J16 7(GPIO_1); JP1 3; U6 4(NC)*

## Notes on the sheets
sheet 1
- 1210
- 1210
- 1210
- 4V
- 0.035 VIA
- TESTPOINTS
- 1210
- 1210
- 1210
- 1210
- 4V
- 1210
- 1210
- 1210
- µModule REGULATOR WITH DIGITAL POWER MANAGEMENT
- 2-21-18
sheet 2
- 1210
- 1210
- 1210
- 4V
- 0.035 VIA
- TESTPOINTS
- 1210
- 1210
- 1210
- 1210
- 4V
- 1210
- 1210
- 1210
- µModule REGULATOR WITH DIGITAL POWER MANAGEMENT
- 2-21-18
sheet 3
- 1210
- 1210
- 1210
- 4V
- 0.035 VIA
- TESTPOINTS
- 1210
- 1210
- 1210
- 1210
- 4V
- 1210
- 1210
- 1210
- µModule REGULATOR WITH DIGITAL POWER MANAGEMENT
- 2-21-18
sheet 4
- 4V
- 1210
- 1210
- 1210
- TESTPOINTS
- 0.035 VIA
- 1210
- 1210
- 1210
- 1210
- Use switch instead of jumpers
- ON
- OFF
- 4V
- 1210
- 1210
- 1210
- OPTIONAL JUMPER FOR SINGLE OUTPUT CONFIGURATION
- µModule REGULATOR WITH DIGITAL POWER MANAGEMENT
- 2-21-18
sheet 5
- ALL PARTS ON THIS PAGE ARE FOR DEMO ONLY, NOT NEEDED IN CUSTOMER DESIGN
- TO DC2086A
- TO DC1613A
- 1206
- PSM STACKING CONNECTORS:
- OPTIONAL CIRCUIT FOR PROGRAMMING
  WITHOUT VIN
- J1, MALE, CONN  HEADER 14POS 2MM R/A GOLD, Molex Connector Corp. 87760-1416
- J2, FEMALE, CONN RECEPT 2MM DUAL R/A 14POS, Sullins Conn.
  NPPN072FJFN-RC
- FAULT1
- PGOOD0
- PGOOD1
- FAULT0
- ALERTB
- 2-21-18
sheet 6
- 1210
- 1210
- 1210
- 4V
- 0.035 VIA
- TESTPOINTS
- 4.5V - 16V
- 35V
- 1210
- 1210
- 1210
- 1210
- ADJUSTABLE
- 4V
- 1210
- 1210
- 1210
- Use switch instead of jumpers
- ON
- NOTE: UNLESS OTHERWISE SPECIFIED
- OFF
- 1.  ALL RESISTORS AND CAPACITORS  ARE 0603.
- *
- CIN10,
  11,12,13
- CIN14,
  15,16,17
- CIN18,
  19,20,21
- COUT60,
  61,64,63
- COUT72,
  73,75,80
- COUT84,
  87,88,93
- COUT58,59,
  62,65,66,67
- ASSY
- Module
- Iout
- C14
- COUT70,71,
  74,77,78,79
- COUT82,83,
  86,89,90,91
- -A
- U1,U2
- 100A
- 10nF
- OPT
- OPT
- OPT
- OPT
- OPT
- OPT
- OPT
- OPT
- OPT
- -B
- U1,U2,U3
- 150A
- 12nF
- 22uF
- OPT
- OPT
- 470uF
- OPT
- OPT
- 100uF
- OPT
- OPT
- -C
- U1,U2,U3,U4
- UP TO 200A
- 18nF
- 22uF
- 22uF
- OPT
- 470uF
- 470uF
- OPT
- 100uF
- 100uF
- OPT
- -D
- U1,U2,U3,U4,U5
- UP TO 250A
- 27nF
- 22uF
- 22uF
- 22uF
- 470uF
- 470uF
- 470uF
- 100uF
- 100uF
- 100uF
- *WHEN VIN <5.75V, SHORT INTVCC to VIN WITH R8=0
  *WHEN EXTVCC IS USED,  R249=OPEN
- µModule REGULATOR WITH DIGITAL POWER MANAGEMENT
- 2-21-18
sheet 7
- ALL PARTS ON THIS PAGE ARE FOR DEMO ONLY, NOT NEEDED IN CUSTOMER DESIGN
- DYNAMIC LOAD CIRCUIT
- VOUT
- PULSE
- INT
- EXT
- 70Hz, 3% Duty Cycle
- IOUT
- 0805
- 2512
- 2512
- 1%
- OPT
- OPT
- BLEEDER LOADS
- 1%
- BIAS
- ON
- OFF
- 2-21-18
- µModule REGULATOR WITH DIGITAL POWER MANAGEMENT
- µModule REGULATOR WITH DIGITAL POWER MANAGEMENT
- µModule REGULATOR WITH DIGITAL POWER MANAGEMENT
- 2-21-18
